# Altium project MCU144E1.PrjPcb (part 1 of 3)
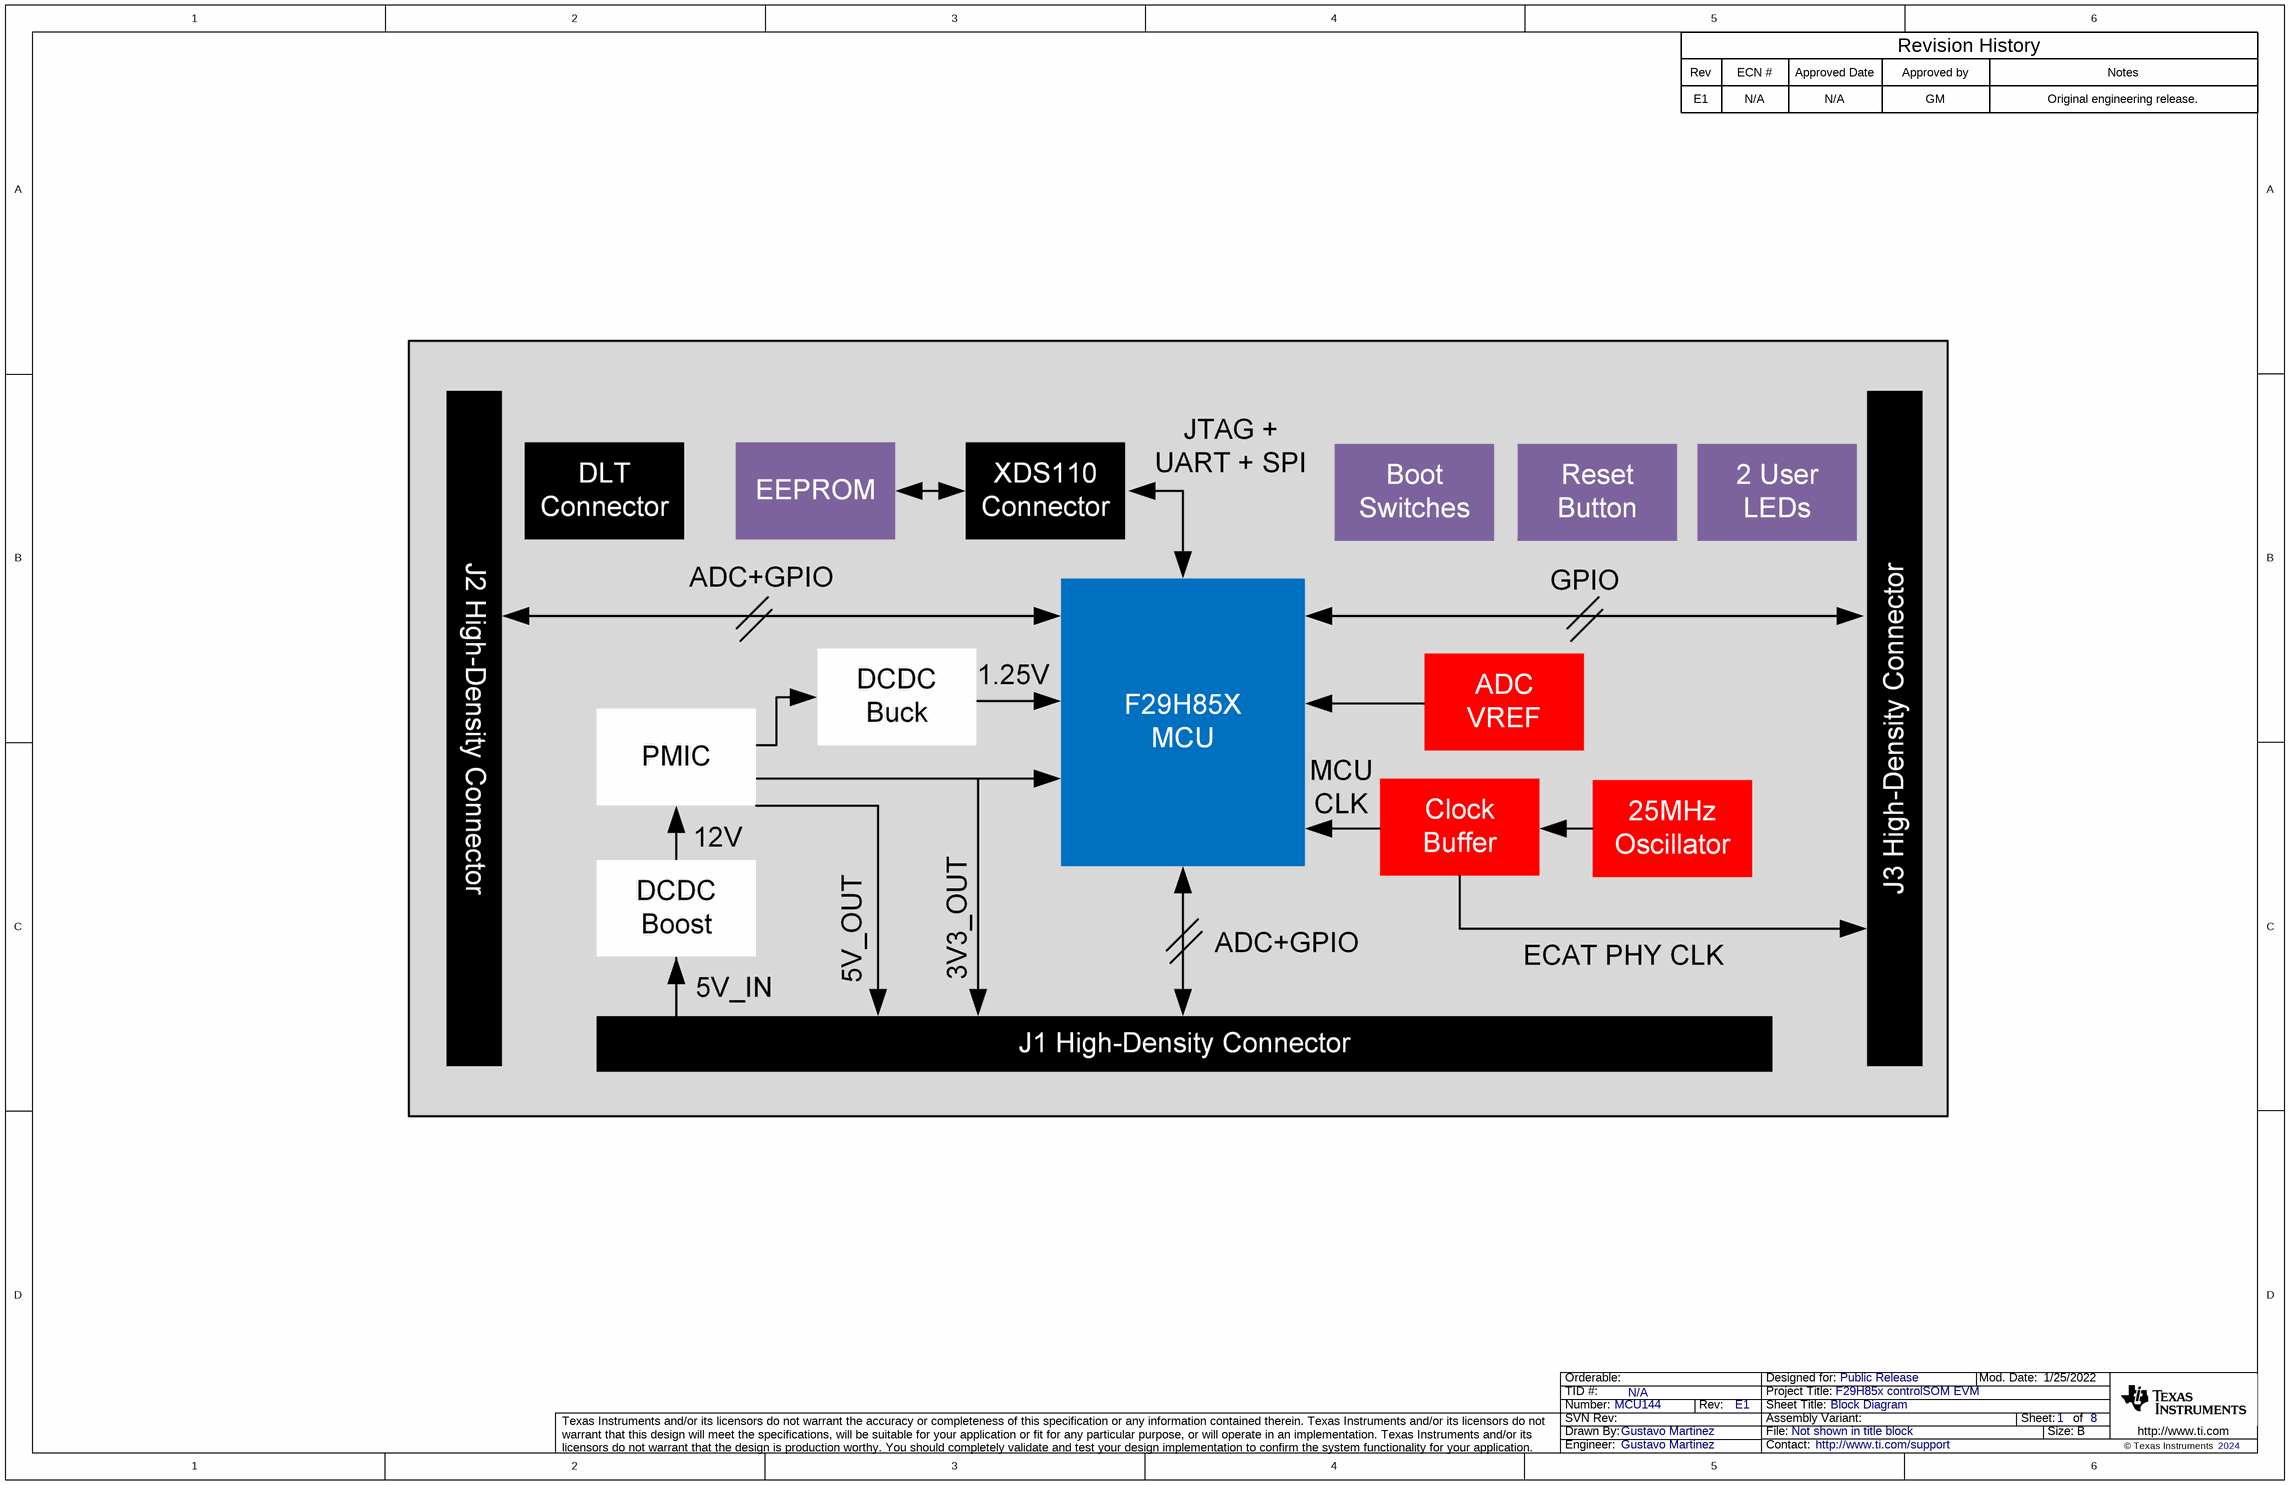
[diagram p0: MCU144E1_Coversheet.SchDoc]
CopyrightYear: 2024; PCB_Layout: Krypton Solutions; PCB_Rev: E1; PRJ_Customer: Public Release; PRJ_Engineer: Gustavo Martinez; PRJ_Number: MCU144; PRJ_Title: F29H85x controlSOM EVM; SCH_Rev: E1; TechSupport: http://www.ti.com/support; TID: N/A
8 sheets, 258 parts. Net scope: global (net labels, ports and power ports of the same name join across sheets).
Board file: MCU144E1.PcbDoc
Sheets:
  MCU144E1_Coversheet.SchDoc
  MCU144E1_GPIO_Power.SchDoc
  MCU144E1_ADC.SchDoc
  MCU144E1_Clock_Reset_Boot.SchDoc
  MCU144E1_SOM_Power.SchDoc
  MCU144E1_Baseboard_Connectors.SchDoc
  MCU144E1_Emulation_Connectors.SchDoc
  MCU144E1_EVM_Hardware.SchDoc

## Sheet MCU144E1_Coversheet.SchDoc: Block Diagram
size 431 x 279 mm; Date: Not shown in title block; ApprovedBy: Not shown in title block; CheckedBy: Not shown in title block; Author: Not shown in title block; CompanyName: Not shown in title block; DrawnBy: Gustavo Martinez; Engineer: Not shown in title block; Organization: Not shown in title block; Address1: Not shown in title block; Address2: Not shown in title block; Address3: Not shown in title block; Address4: Not shown in title block; DocumentNumber: 1; Revision: Use project parameter SCH_Rev; SheetNumber: 1; SheetTotal: 8; PageSetup: Record=PageOptions¦CenterHorizontal=True¦CenterVertical=True¦PrintScale=1.00¦XCorrection=1.00¦YCorrection=1.00¦PrintKind=0¦BorderSize=5000000¦LeftOffset=0¦BottomOffset=0¦Orientation=2¦PaperLength=1000¦PaperWidth=1000¦Scale=100¦PaperSource=15¦PrintQuality=600¦MediaType=1¦DitherType=10¦PaperKind=Letter¦PrintScaleMode=1

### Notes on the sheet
- Rev
- E1
- ECN #
- N/A
- Approved Date
- Approved by
- GM
- Revision History
- Notes
- Original engineering release.

## Sheet MCU144E1_GPIO_Power.SchDoc: GPIO and Power
size 431 x 279 mm; Date: Not shown in title block; ApprovedBy: Not shown in title block; CheckedBy: Not shown in title block; Author: Not shown in title block; CompanyName: Not shown in title block; DrawnBy: Gustavo Martinez; Engineer: Not shown in title block; Organization: Not shown in title block; Address1: Not shown in title block; Address2: Not shown in title block; Address3: Not shown in title block; Address4: Not shown in title block; DocumentNumber: 8; Revision: Use project parameter SCH_Rev; SheetNumber: 2; SheetTotal: 8; PageSetup: Record=PageOptions¦CenterHorizontal=True¦CenterVertical=True¦PrintScale=1.00¦XCorrection=1.00¦YCorrection=1.00¦PrintKind=0¦BorderSize=5000000¦LeftOffset=0¦BottomOffset=0¦Orientation=2¦PaperLength=1000¦PaperWidth=1000¦Scale=100¦PaperSource=15¦PrintQuality=600¦MediaType=1¦DitherType=10¦PaperKind=Letter¦PrintScaleMode=1
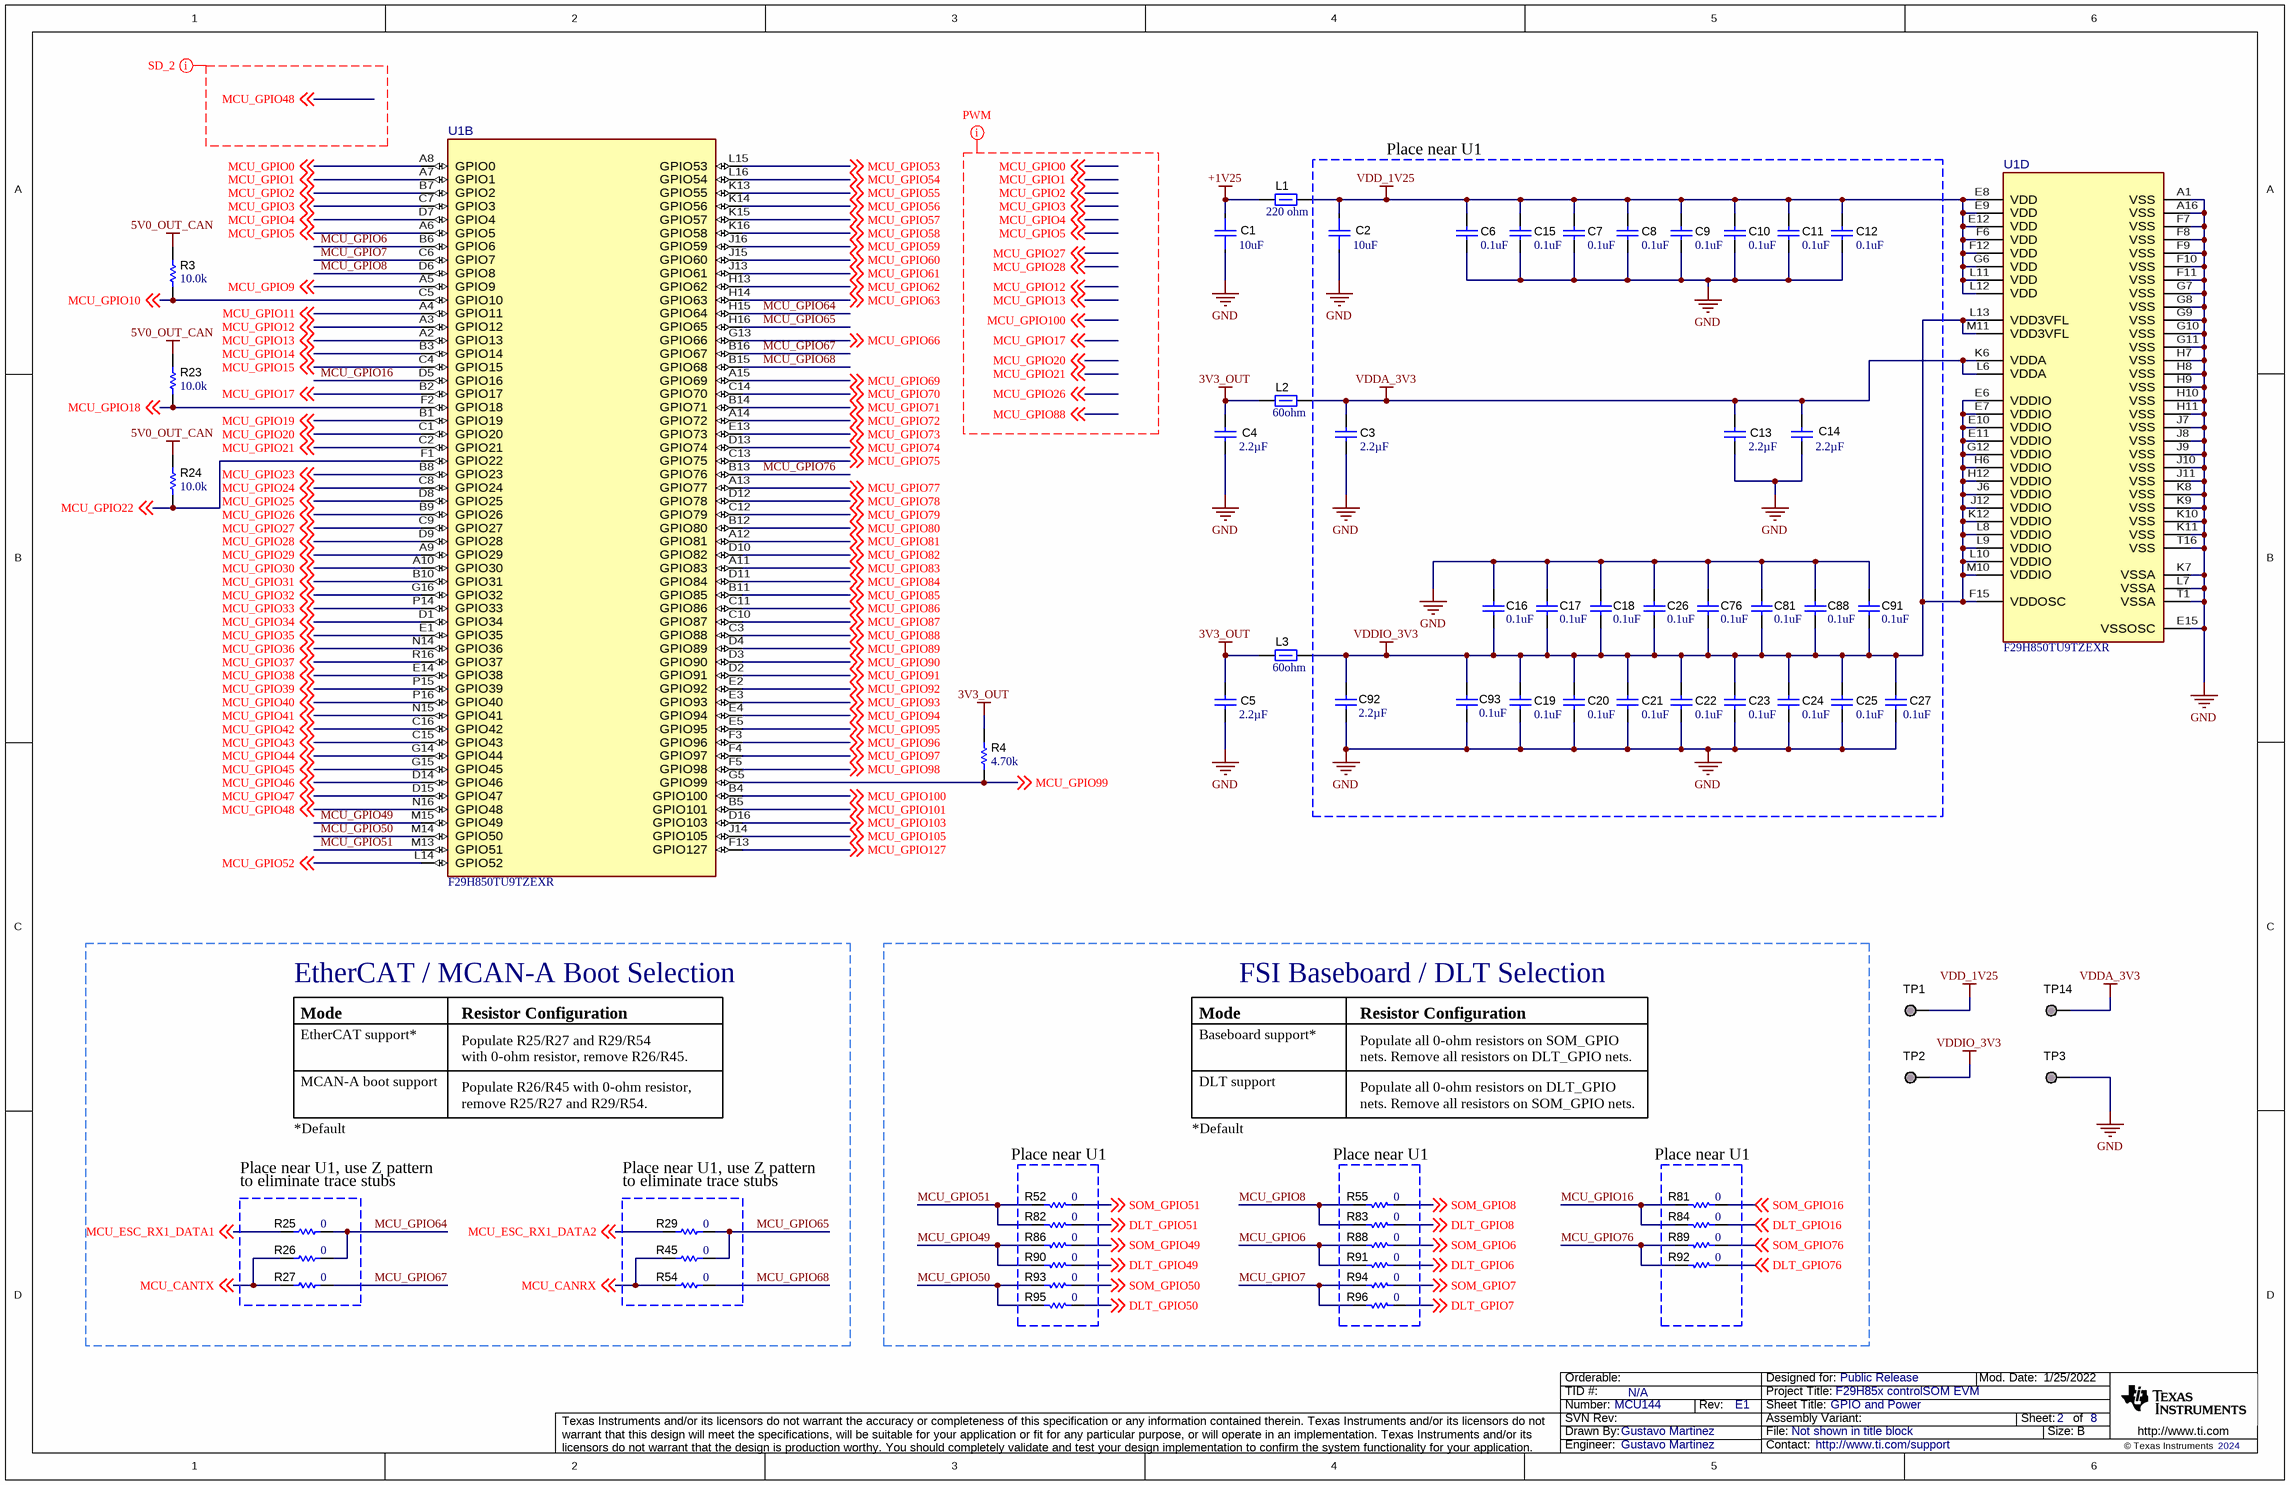
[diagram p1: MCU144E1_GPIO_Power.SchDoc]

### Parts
C1  ValueDisplayed: 10uF  [FP-GRM155R61A106ME18D_0402-MFG]  (hidden comment: GRM155R61A106ME18D)
C2  ValueDisplayed: 10uF  [FP-GRM155R61A106ME18D_0402-MFG]  (hidden comment: GRM155R61A106ME18D)
C3  ValueDisplayed: 2.2µF  [0402]  (hidden comment: GRM155R61E225ME15D)
C4  ValueDisplayed: 2.2µF  [0402]  (hidden comment: GRM155R61E225ME15D)
C5  ValueDisplayed: 2.2µF  [0402]  (hidden comment: GRM155R61E225ME15D)
C6  ValueDisplayed: 0.1uF  [0402]  (hidden comment: GRM155R71E104KE14D)
C7  ValueDisplayed: 0.1uF  [0402]  (hidden comment: GRM155R71E104KE14D)
C8  ValueDisplayed: 0.1uF  [0402]  (hidden comment: GRM155R71E104KE14D)
C9  ValueDisplayed: 0.1uF  [0402]  (hidden comment: GRM155R71E104KE14D)
C10  ValueDisplayed: 0.1uF  [0402]  (hidden comment: GRM155R71E104KE14D)
C11  ValueDisplayed: 0.1uF  [0402]  (hidden comment: GRM155R71E104KE14D)
C12  ValueDisplayed: 0.1uF  [0402]  (hidden comment: GRM155R71E104KE14D)
C13  ValueDisplayed: 2.2µF  [0402]  (hidden comment: GRM155R61E225ME15D)
C14  ValueDisplayed: 2.2µF  [0402]  (hidden comment: GRM155R61E225ME15D)
C15  ValueDisplayed: 0.1uF  [0402]  (hidden comment: GRM155R71E104KE14D)
C16  ValueDisplayed: 0.1uF  [0402]  (hidden comment: GRM155R71E104KE14D)
C17  ValueDisplayed: 0.1uF  [0402]  (hidden comment: GRM155R71E104KE14D)
C18  ValueDisplayed: 0.1uF  [0402]  (hidden comment: GRM155R71E104KE14D)
C19  ValueDisplayed: 0.1uF  [0402]  (hidden comment: GRM155R71E104KE14D)
C20  ValueDisplayed: 0.1uF  [0402]  (hidden comment: GRM155R71E104KE14D)
C21  ValueDisplayed: 0.1uF  [0402]  (hidden comment: GRM155R71E104KE14D)
C22  ValueDisplayed: 0.1uF  [0402]  (hidden comment: GRM155R71E104KE14D)
C23  ValueDisplayed: 0.1uF  [0402]  (hidden comment: GRM155R71E104KE14D)
C24  ValueDisplayed: 0.1uF  [0402]  (hidden comment: GRM155R71E104KE14D)
C25  ValueDisplayed: 0.1uF  [0402]  (hidden comment: GRM155R71E104KE14D)
C26  ValueDisplayed: 0.1uF  [0402]  (hidden comment: GRM155R71E104KE14D)
C27  ValueDisplayed: 0.1uF  [0402]  (hidden comment: GRM155R71E104KE14D)
C76  ValueDisplayed: 0.1uF  [0402]  (hidden comment: GRM155R71E104KE14D)
C81  ValueDisplayed: 0.1uF  [0402]  (hidden comment: GRM155R71E104KE14D)
C88  ValueDisplayed: 0.1uF  [0402]  (hidden comment: GRM155R71E104KE14D)
C91  ValueDisplayed: 0.1uF  [0402]  (hidden comment: GRM155R71E104KE14D)
C92  ValueDisplayed: 2.2µF  [0402]  (hidden comment: GRM155R61E225ME15D)
C93  ValueDisplayed: 0.1uF  [0402]  (hidden comment: GRM155R71E104KE14D)
L1  value 220 ohm  [0805_HV]  (hidden comment: BLM21PG221SN1D)
L2  60ohm  [0603]
L3  60ohm  [0603]
R3  value 10.0k  [0402]  (hidden comment: AC0402FR-0710KL)
R4  ValueDisplayed: 4.70k  [0402]  (hidden comment: CRG0402F4K7)
R23  value 10.0k  [0402]  (hidden comment: AC0402FR-0710KL)
R24  value 10.0k  [0402]  (hidden comment: AC0402FR-0710KL)
R25  ValueDisplayed: 0  [0402]  (hidden comment: CRCW04020000Z0ED)
R26  ValueDisplayed: 0  [0402]  (hidden comment: CRCW04020000Z0ED)
R27  ValueDisplayed: 0  [0402]  (hidden comment: CRCW04020000Z0ED)
R29  ValueDisplayed: 0  [0402]  (hidden comment: CRCW04020000Z0ED)
R45  ValueDisplayed: 0  [0402]  (hidden comment: CRCW04020000Z0ED)
R52  ValueDisplayed: 0  [0402]  (hidden comment: CRCW04020000Z0ED)
R54  ValueDisplayed: 0  [0402]  (hidden comment: CRCW04020000Z0ED)
R55  ValueDisplayed: 0  [0402]  (hidden comment: CRCW04020000Z0ED)
R81  ValueDisplayed: 0  [0402]  (hidden comment: CRCW04020000Z0ED)
R82  ValueDisplayed: 0  [0402]  (hidden comment: CRCW04020000Z0ED)
R83  ValueDisplayed: 0  [0402]  (hidden comment: CRCW04020000Z0ED)
R84  ValueDisplayed: 0  [0402]  (hidden comment: CRCW04020000Z0ED)
R86  ValueDisplayed: 0  [0402]  (hidden comment: CRCW04020000Z0ED)
R88  ValueDisplayed: 0  [0402]  (hidden comment: CRCW04020000Z0ED)
R89  ValueDisplayed: 0  [0402]  (hidden comment: CRCW04020000Z0ED)
R90  ValueDisplayed: 0  [0402]  (hidden comment: CRCW04020000Z0ED)
R91  ValueDisplayed: 0  [0402]  (hidden comment: CRCW04020000Z0ED)
R92  ValueDisplayed: 0  [0402]  (hidden comment: CRCW04020000Z0ED)
R93  ValueDisplayed: 0  [0402]  (hidden comment: CRCW04020000Z0ED)
R94  ValueDisplayed: 0  [0402]  (hidden comment: CRCW04020000Z0ED)
R95  ValueDisplayed: 0  [0402]  (hidden comment: CRCW04020000Z0ED)
R96  ValueDisplayed: 0  [0402]  (hidden comment: CRCW04020000Z0ED)
TP1  CMP-0078143-4  [TESTPOINT]  (value not drawn)  (no BOM)
TP2  CMP-0078143-4  [TESTPOINT]  (value not drawn)  (no BOM)
TP3  CMP-0078143-4  [TESTPOINT]  (value not drawn)  (no BOM)
TP14  CMP-0078143-4  [TESTPOINT]  (value not drawn)  (no BOM)
U1  F29H850TU9TZEXR  [ZEX0256A-MFG]  (parts B,D of 4)

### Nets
3V3_OUT: C4.1 C5.1 L2.1 L3.1 R4.2
5V0_OUT_CAN: R3.2 R23.2 R24.2
+1V25: C1.2 L1.1
GND: C1.1 C2.1 C3.2 C4.2 C5.2 C6.2 C7.2 C8.2 C9.2 C10.2 C11.2 C12.2 C13.2 C14.2 C15.2 C16.2 C17.2 C18.2 C19.2 C20.2 C21.2 C22.2 C23.2 C24.2 C25.2 C26.2 C27.2 C76.2 C81.2 C88.2 C91.2 C92.1 C93.1 TP3.1 U1.A1(VSS) U1.A16(VSS) U1.E15(VSSOSC) U1.F7(VSS) U1.F8(VSS) U1.F9(VSS) U1.F10(VSS) U1.F11(VSS) U1.G7(VSS) U1.G8(VSS) U1.G9(VSS) U1.G10(VSS) U1.G11(VSS) U1.H7(VSS) U1.H8(VSS) U1.H9(VSS) U1.H10(VSS) U1.H11(VSS) U1.J7(VSS) U1.J8(VSS) U1.J9(VSS) U1.J10(VSS) U1.J11(VSS) U1.K7(VSSA) U1.K8(VSS) U1.K9(VSS) U1.K10(VSS) U1.K11(VSS) U1.L7(VSSA) U1.T1(VSSA) U1.T16(VSS)
VDD_1V25: C2.2 C6.1 C7.1 C8.1 C9.1 C10.1 C11.1 C12.1 C15.1 L1.2 TP1.1 U1.E8(VDD) U1.E9(VDD) U1.E12(VDD) U1.F6(VDD) U1.F12(VDD) U1.G6(VDD) U1.L11(VDD) U1.L12(VDD)
VDDA_3V3: C3.1 C13.1 C14.1 L2.2 TP14.1 U1.K6(VDDA) U1.L6(VDDA)
VDDIO_3V3: C16.1 C17.1 C18.1 C19.1 C20.1 C21.1 C22.1 C23.1 C24.1 C25.1 C26.1 C27.1 C76.1 C81.1 C88.1 C91.1 C92.2 C93.2 L3.2 TP2.1 U1.E6(VDDIO) U1.E7(VDDIO) U1.E10(VDDIO) U1.E11(VDDIO) U1.F15(VDDOSC) U1.G12(VDDIO) U1.H6(VDDIO) U1.H12(VDDIO) U1.J6(VDDIO) U1.J12(VDDIO) U1.K12(VDDIO) U1.L8(VDDIO) U1.L9(VDDIO) U1.L10(VDDIO) U1.L13(VDD3VFL) U1.M10(VDDIO) U1.M11(VDD3VFL)
DLT_GPIO6: R91.1 ; off-sheet DLT_GPIO6
DLT_GPIO7: R96.1 ; off-sheet DLT_GPIO7
DLT_GPIO8: R83.1 ; off-sheet DLT_GPIO8
DLT_GPIO16: R84.1 ; off-sheet DLT_GPIO16
DLT_GPIO49: R90.1 ; off-sheet DLT_GPIO49
DLT_GPIO50: R95.1 ; off-sheet DLT_GPIO50
DLT_GPIO51: R82.1 ; off-sheet DLT_GPIO51
DLT_GPIO76: R92.1 ; off-sheet DLT_GPIO76
MCU_CANRX: R45.1 R54.1 ; off-sheet MCU_CANRX
MCU_CANTX: R26.1 R27.1 ; off-sheet MCU_CANTX
MCU_ESC_RX1_DATA1: R25.1 ; off-sheet MCU_ESC_RX1_DATA1
MCU_ESC_RX1_DATA2: R29.1 ; off-sheet MCU_ESC_RX1_DATA2
MCU_GPIO0: U1.A8(GPIO0) ; off-sheet MCU_GPIO0
MCU_GPIO1: U1.A7(GPIO1) ; off-sheet MCU_GPIO1
MCU_GPIO2: U1.B7(GPIO2) ; off-sheet MCU_GPIO2
MCU_GPIO3: U1.C7(GPIO3) ; off-sheet MCU_GPIO3
MCU_GPIO4: U1.D7(GPIO4) ; off-sheet MCU_GPIO4
MCU_GPIO5: U1.A6(GPIO5) ; off-sheet MCU_GPIO5
MCU_GPIO6: R88.2 R91.2 U1.B6(GPIO6)
MCU_GPIO7: R94.2 R96.2 U1.C6(GPIO7)
MCU_GPIO8: R55.2 R83.2 U1.D6(GPIO8)
MCU_GPIO9: U1.A5(GPIO9) ; off-sheet MCU_GPIO9
MCU_GPIO10: R3.1 U1.C5(GPIO10) ; off-sheet MCU_GPIO10
MCU_GPIO11: U1.A4(GPIO11) ; off-sheet MCU_GPIO11
MCU_GPIO12: U1.A3(GPIO12) ; off-sheet MCU_GPIO12
MCU_GPIO13: U1.A2(GPIO13) ; off-sheet MCU_GPIO13
MCU_GPIO14: U1.B3(GPIO14) ; off-sheet MCU_GPIO14
MCU_GPIO15: U1.C4(GPIO15) ; off-sheet MCU_GPIO15
MCU_GPIO16: R81.2 R84.2 U1.D5(GPIO16)
MCU_GPIO17: U1.B2(GPIO17) ; off-sheet MCU_GPIO17
MCU_GPIO18: R23.1 U1.F2(GPIO18) ; off-sheet MCU_GPIO18
MCU_GPIO19: U1.B1(GPIO19) ; off-sheet MCU_GPIO19
MCU_GPIO20: U1.C1(GPIO20) ; off-sheet MCU_GPIO20
MCU_GPIO21: U1.C2(GPIO21) ; off-sheet MCU_GPIO21
MCU_GPIO22: R24.1 U1.F1(GPIO22) ; off-sheet MCU_GPIO22
MCU_GPIO23: U1.B8(GPIO23) ; off-sheet MCU_GPIO23
MCU_GPIO24: U1.C8(GPIO24) ; off-sheet MCU_GPIO24
MCU_GPIO25: U1.D8(GPIO25) ; off-sheet MCU_GPIO25
MCU_GPIO26: U1.B9(GPIO26) ; off-sheet MCU_GPIO26
MCU_GPIO27: U1.C9(GPIO27) ; off-sheet MCU_GPIO27
MCU_GPIO28: U1.D9(GPIO28) ; off-sheet MCU_GPIO28
MCU_GPIO29: U1.A9(GPIO29) ; off-sheet MCU_GPIO29
MCU_GPIO30: U1.A10(GPIO30) ; off-sheet MCU_GPIO30
MCU_GPIO31: U1.B10(GPIO31) ; off-sheet MCU_GPIO31
MCU_GPIO32: U1.G16(GPIO32) ; off-sheet MCU_GPIO32
MCU_GPIO33: U1.P14(GPIO33) ; off-sheet MCU_GPIO33
MCU_GPIO34: U1.D1(GPIO34) ; off-sheet MCU_GPIO34
MCU_GPIO35: U1.E1(GPIO35) ; off-sheet MCU_GPIO35
MCU_GPIO36: U1.N14(GPIO36) ; off-sheet MCU_GPIO36
MCU_GPIO37: U1.R16(GPIO37) ; off-sheet MCU_GPIO37
MCU_GPIO38: U1.E14(GPIO38) ; off-sheet MCU_GPIO38
MCU_GPIO39: U1.P15(GPIO39) ; off-sheet MCU_GPIO39
MCU_GPIO40: U1.P16(GPIO40) ; off-sheet MCU_GPIO40
MCU_GPIO41: U1.N15(GPIO41) ; off-sheet MCU_GPIO41
MCU_GPIO42: U1.C16(GPIO42) ; off-sheet MCU_GPIO42
MCU_GPIO43: U1.C15(GPIO43) ; off-sheet MCU_GPIO43
MCU_GPIO44: U1.G14(GPIO44) ; off-sheet MCU_GPIO44
MCU_GPIO45: U1.G15(GPIO45) ; off-sheet MCU_GPIO45
MCU_GPIO46: U1.D14(GPIO46) ; off-sheet MCU_GPIO46
MCU_GPIO47: U1.D15(GPIO47) ; off-sheet MCU_GPIO47
MCU_GPIO48: U1.N16(GPIO48) ; off-sheet MCU_GPIO48
MCU_GPIO49: R86.2 R90.2 U1.M15(GPIO49)
MCU_GPIO50: R93.2 R95.2 U1.M14(GPIO50)
MCU_GPIO51: R52.2 R82.2 U1.M13(GPIO51)
MCU_GPIO52: U1.L14(GPIO52) ; off-sheet MCU_GPIO52
MCU_GPIO53: U1.L15(GPIO53) ; off-sheet MCU_GPIO53
MCU_GPIO54: U1.L16(GPIO54) ; off-sheet MCU_GPIO54
MCU_GPIO55: U1.K13(GPIO55) ; off-sheet MCU_GPIO55
MCU_GPIO56: U1.K14(GPIO56) ; off-sheet MCU_GPIO56
MCU_GPIO57: U1.K15(GPIO57) ; off-sheet MCU_GPIO57
MCU_GPIO58: U1.K16(GPIO58) ; off-sheet MCU_GPIO58
MCU_GPIO59: U1.J16(GPIO59) ; off-sheet MCU_GPIO59
MCU_GPIO60: U1.J15(GPIO60) ; off-sheet MCU_GPIO60
MCU_GPIO61: U1.J13(GPIO61) ; off-sheet MCU_GPIO61
MCU_GPIO62: U1.H13(GPIO62) ; off-sheet MCU_GPIO62
MCU_GPIO63: U1.H14(GPIO63) ; off-sheet MCU_GPIO63
MCU_GPIO64: R25.2 R26.2 U1.H15(GPIO64)
MCU_GPIO65: R29.2 R45.2 U1.H16(GPIO65)
MCU_GPIO66: U1.G13(GPIO66) ; off-sheet MCU_GPIO66
MCU_GPIO67: R27.2 U1.B16(GPIO67)
MCU_GPIO68: R54.2 U1.B15(GPIO68)
MCU_GPIO69: U1.A15(GPIO69) ; off-sheet MCU_GPIO69
MCU_GPIO70: U1.C14(GPIO70) ; off-sheet MCU_GPIO70
MCU_GPIO71: U1.B14(GPIO71) ; off-sheet MCU_GPIO71
MCU_GPIO72: U1.A14(GPIO72) ; off-sheet MCU_GPIO72
MCU_GPIO73: U1.E13(GPIO73) ; off-sheet MCU_GPIO73
MCU_GPIO74: U1.D13(GPIO74) ; off-sheet MCU_GPIO74
MCU_GPIO75: U1.C13(GPIO75) ; off-sheet MCU_GPIO75
MCU_GPIO76: R89.2 R92.2 U1.B13(GPIO76)
MCU_GPIO77: U1.A13(GPIO77) ; off-sheet MCU_GPIO77
MCU_GPIO78: U1.D12(GPIO78) ; off-sheet MCU_GPIO78
MCU_GPIO79: U1.C12(GPIO79) ; off-sheet MCU_GPIO79
MCU_GPIO80: U1.B12(GPIO80) ; off-sheet MCU_GPIO80
MCU_GPIO81: U1.A12(GPIO81) ; off-sheet MCU_GPIO81
MCU_GPIO82: U1.D10(GPIO82) ; off-sheet MCU_GPIO82
MCU_GPIO83: U1.A11(GPIO83) ; off-sheet MCU_GPIO83
MCU_GPIO84: U1.D11(GPIO84) ; off-sheet MCU_GPIO84
MCU_GPIO85: U1.B11(GPIO85) ; off-sheet MCU_GPIO85
MCU_GPIO86: U1.C11(GPIO86) ; off-sheet MCU_GPIO86
MCU_GPIO87: U1.C10(GPIO87) ; off-sheet MCU_GPIO87
MCU_GPIO88: U1.C3(GPIO88) ; off-sheet MCU_GPIO88
MCU_GPIO89: U1.D4(GPIO89) ; off-sheet MCU_GPIO89
MCU_GPIO90: U1.D3(GPIO90) ; off-sheet MCU_GPIO90
MCU_GPIO91: U1.D2(GPIO91) ; off-sheet MCU_GPIO91
MCU_GPIO92: U1.E2(GPIO92) ; off-sheet MCU_GPIO92
MCU_GPIO93: U1.E3(GPIO93) ; off-sheet MCU_GPIO93
MCU_GPIO94: U1.E4(GPIO94) ; off-sheet MCU_GPIO94
MCU_GPIO95: U1.E5(GPIO95) ; off-sheet MCU_GPIO95
MCU_GPIO96: U1.F3(GPIO96) ; off-sheet MCU_GPIO96
MCU_GPIO97: U1.F4(GPIO97) ; off-sheet MCU_GPIO97
MCU_GPIO98: U1.F5(GPIO98) ; off-sheet MCU_GPIO98
MCU_GPIO99: R4.1 U1.G5(GPIO99) ; off-sheet MCU_GPIO99
MCU_GPIO100: U1.B4(GPIO100) ; off-sheet MCU_GPIO100
MCU_GPIO101: U1.B5(GPIO101) ; off-sheet MCU_GPIO101
MCU_GPIO103: U1.D16(GPIO103) ; off-sheet MCU_GPIO103
MCU_GPIO105: U1.J14(GPIO105) ; off-sheet MCU_GPIO105
MCU_GPIO127: U1.F13(GPIO127) ; off-sheet MCU_GPIO127
SOM_GPIO6: R88.1 ; off-sheet SOM_GPIO6
SOM_GPIO7: R94.1 ; off-sheet SOM_GPIO7
SOM_GPIO8: R55.1 ; off-sheet SOM_GPIO8
SOM_GPIO16: R81.1 ; off-sheet SOM_GPIO16
SOM_GPIO49: R86.1 ; off-sheet SOM_GPIO49
SOM_GPIO50: R93.1 ; off-sheet SOM_GPIO50
SOM_GPIO51: R52.1 ; off-sheet SOM_GPIO51
SOM_GPIO76: R89.1 ; off-sheet SOM_GPIO76

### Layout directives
net class SD_2: MCU_GPIO48
net class PWM: MCU_GPIO0, MCU_GPIO1, MCU_GPIO2, MCU_GPIO3, MCU_GPIO4, MCU_GPIO5, MCU_GPIO12, MCU_GPIO13, MCU_GPIO17, MCU_GPIO20, MCU_GPIO21, MCU_GPIO26, MCU_GPIO27, MCU_GPIO28, MCU_GPIO88, MCU_GPIO100

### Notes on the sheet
- Place near U1
- EtherCAT / MCAN-A Boot Selection
- Mode
- Resistor Configuration
- FSI Baseboard / DLT Selection
- EtherCAT support*
- MCAN-A boot support
- Populate R25/R27 and R29/R54
  with 0-ohm resistor, remove R26/R45.
- Populate R26/R45 with 0-ohm resistor, remove R25/R27 and R29/R54.
- Baseboard support*
- DLT support
- Populate all 0-ohm resistors on SOM_GPIO nets. Remove all resistors on DLT_GPIO nets.
- Populate all 0-ohm resistors on DLT_GPIO nets. Remove all resistors on SOM_GPIO nets.
- *Default
- Place near U1, use Z pattern
- (near R25) to eliminate trace stubs
- (near R29) to eliminate trace stubs

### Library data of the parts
C1 C2 = CMP-0120207-1: 10 µF ±20% 10V Ceramic Capacitor X5R 0402 (1005 Metric); Manufacturer: Murata; Cap_F: 10µF; TempCo: 15%; SizeZ_mm: 0.7mm; Value: 10µF; AEC Qualified: No
C3-C5 C13 C14 C92 = CMP-0081010-1: CAP, CERM, 2.2 µF, 25 V,+/- 20%, X5R, 0402; Manufacturer: MuRata; TaMin_C: -55°C; Polarized: N; SizeAreaWB_mm2: 3; U/M: EA; Value: 2.2uF; TaMax_C: 85°C; SizeZ_mm: 0.6; SizeX_mm: 1; SizeY_mm: 0.5; Value2: 25V; AEC Category: Q200
C6-C12 C15-C27 C76 C81 C88 C91 C93 = CMP-0006659-2: CAP, CERM, 0.1 uF, 25 V, +/- 10%, X7R, 0402; Manufacturer: MuRata; TaMin_C: -55°C; Polarized: N; SizeAreaWB_mm2: 3; Value1: Unknown; U/M: EA; Value: 0.1uF; TaMax_C: 125°C; SizeZ_mm: 0.6; SizeX_mm: 1; SizeY_mm: 0.5; Value2: 25V; Cap_F: 100nF; AEC Category: Q200
L1 = CMP-0003363-1: Ferrite Bead, 220 ohm @ 100 MHz, 2 A, 0805; Manufacturer: MuRata; ZTyp@100MHz_Ohm: 220; SizeAreaWB_mm2: 6.75; DCR_ohm: 0.045; Value1: 0.045 ohm; Imax_A: 2A; SizeZ_mm: 1.45; SizeX_mm: 2; SizeY_mm: 1.25; SizeArea_mm2: 2.5
L2 L3 = CMP-0003173-2: Ferrite Bead, 60 ohm @ 100 MHz, 3 A, 0603; Manufacturer: Wurth Elektronik; PartNumber: 742792602; Ztyp@1GHz_Ohm: 110.436; ZTyp@100MHz_Ohm: 60; SizeAreaWB_mm2: 4.68; DCR_ohm: 0.04; Value1: 0.04 ohm; Imax_A: 3A; SizeZ_mm: 1; SizeX_mm: 1.6; SizeY_mm: 0.8; SizeArea_mm2: 1.28
R3 R23 R24 = CMP-0077731-1: RES, 10.0 k, 1%, 0.063 W, AEC-Q200 Grade 0, 0402; Manufacturer: Yageo America; Power_W: 63mW; TempCo: 100 ppm/C; Value_Code: 10k0; U/M: EA; EIA_Code: E96; Res_ohm: 10k; SizeX_mm: 1.0; SizeY_mm: 0.5; SizeZ_mm: 0.6; Value2: 0.063W; AEC Qualified: Y; VDC_V: 50V; AEC Grade: 0; AEC Category: Q200
R4 = CMP-0026631-1: RES, 4.70 k, 1%, 0.063 W, 0402; Manufacturer: TE Connectivity; Power_W: 63mW; TempCo: 100 ppm/C; Value_Code: 4k70; U/M: EA; Value: 4.70k; Res_ohm: 4.7k; SizeX_mm: 1; SizeY_mm: 0.5; SizeZ_mm: 0.6; Value2: 0.063W; AEC Qualified: N; AEC Category: Q200
R25-R27 R29 R45 R52 R54 R55 R81-R84 R86 R88-R96 = CMP-0026822-3: RES, 0, 5%, 0.063 W, AEC-Q200 Grade 0, 0402; Manufacturer: Vishay-Dale; Power_W: 63mW; TempCo: 200 ppm/C; Value_Code: 0000; Value: 0; EIA_Code: E24; SizeX_mm: 1; SizeY_mm: 0.5; SizeZ_mm: 0.6; Value2: 0.063W; AEC Qualified: Y; AEC Category: Q200; VDC_V: 50V
TP1-TP3 TP14 = CMP-0078143-4: TEST POINT.  No entry in BOM.
U1 = CMP-0121934-2: Real-Time Microcontroller; Manufacturer: Texas Instruments; SizeZ_mm: 1.3mm; AEC Qualified: No; Core Architecture: C29x; Data Bus Width: 64bits; Frequency_Fixed: 200MHz; Interface: I2C,SPI,UART,CAN,LIN,IrDA,Other; Max Supply Voltage: 3.63V; Memory Size: 4MBytes; Memory Type: FLASH; Min Supply Voltage: 1.14V; Number Of A/D Converters: 5; Number Of Cores: 3; Number Of Ethernet Channels: 1; Number Of I2C Channels: 2; Number Of Pwm Channels: 36; Number Of Timers/Counters: 12; Number Of Uart Channels: 6; Ram Size: 452KBytes; Standoff Height: 0.25mm; TaMax_C: +105°C; TaMin_C: -40°C; TJmax_C: +125°C; AEC Category: Q200; CompType: IC

## Sheet MCU144E1_ADC.SchDoc: ADC
size 431 x 279 mm; DrawnBy: Gustavo Martinez; DocumentNumber: 9; SheetNumber: 3; SheetTotal: 8; PageSetup: Record=PageOptions¦CenterHorizontal=True¦CenterVertical=True¦PrintScale=1.00¦XCorrection=1.00¦YCorrection=1.00¦PrintKind=0¦BorderSize=5000000¦LeftOffset=0¦BottomOffset=0¦Orientation=2¦PaperLength=1000¦PaperWidth=1000¦Scale=100¦PaperSource=15¦PrintQuality=600¦MediaType=1¦DitherType=10¦PaperKind=Letter¦PrintScaleMode=1
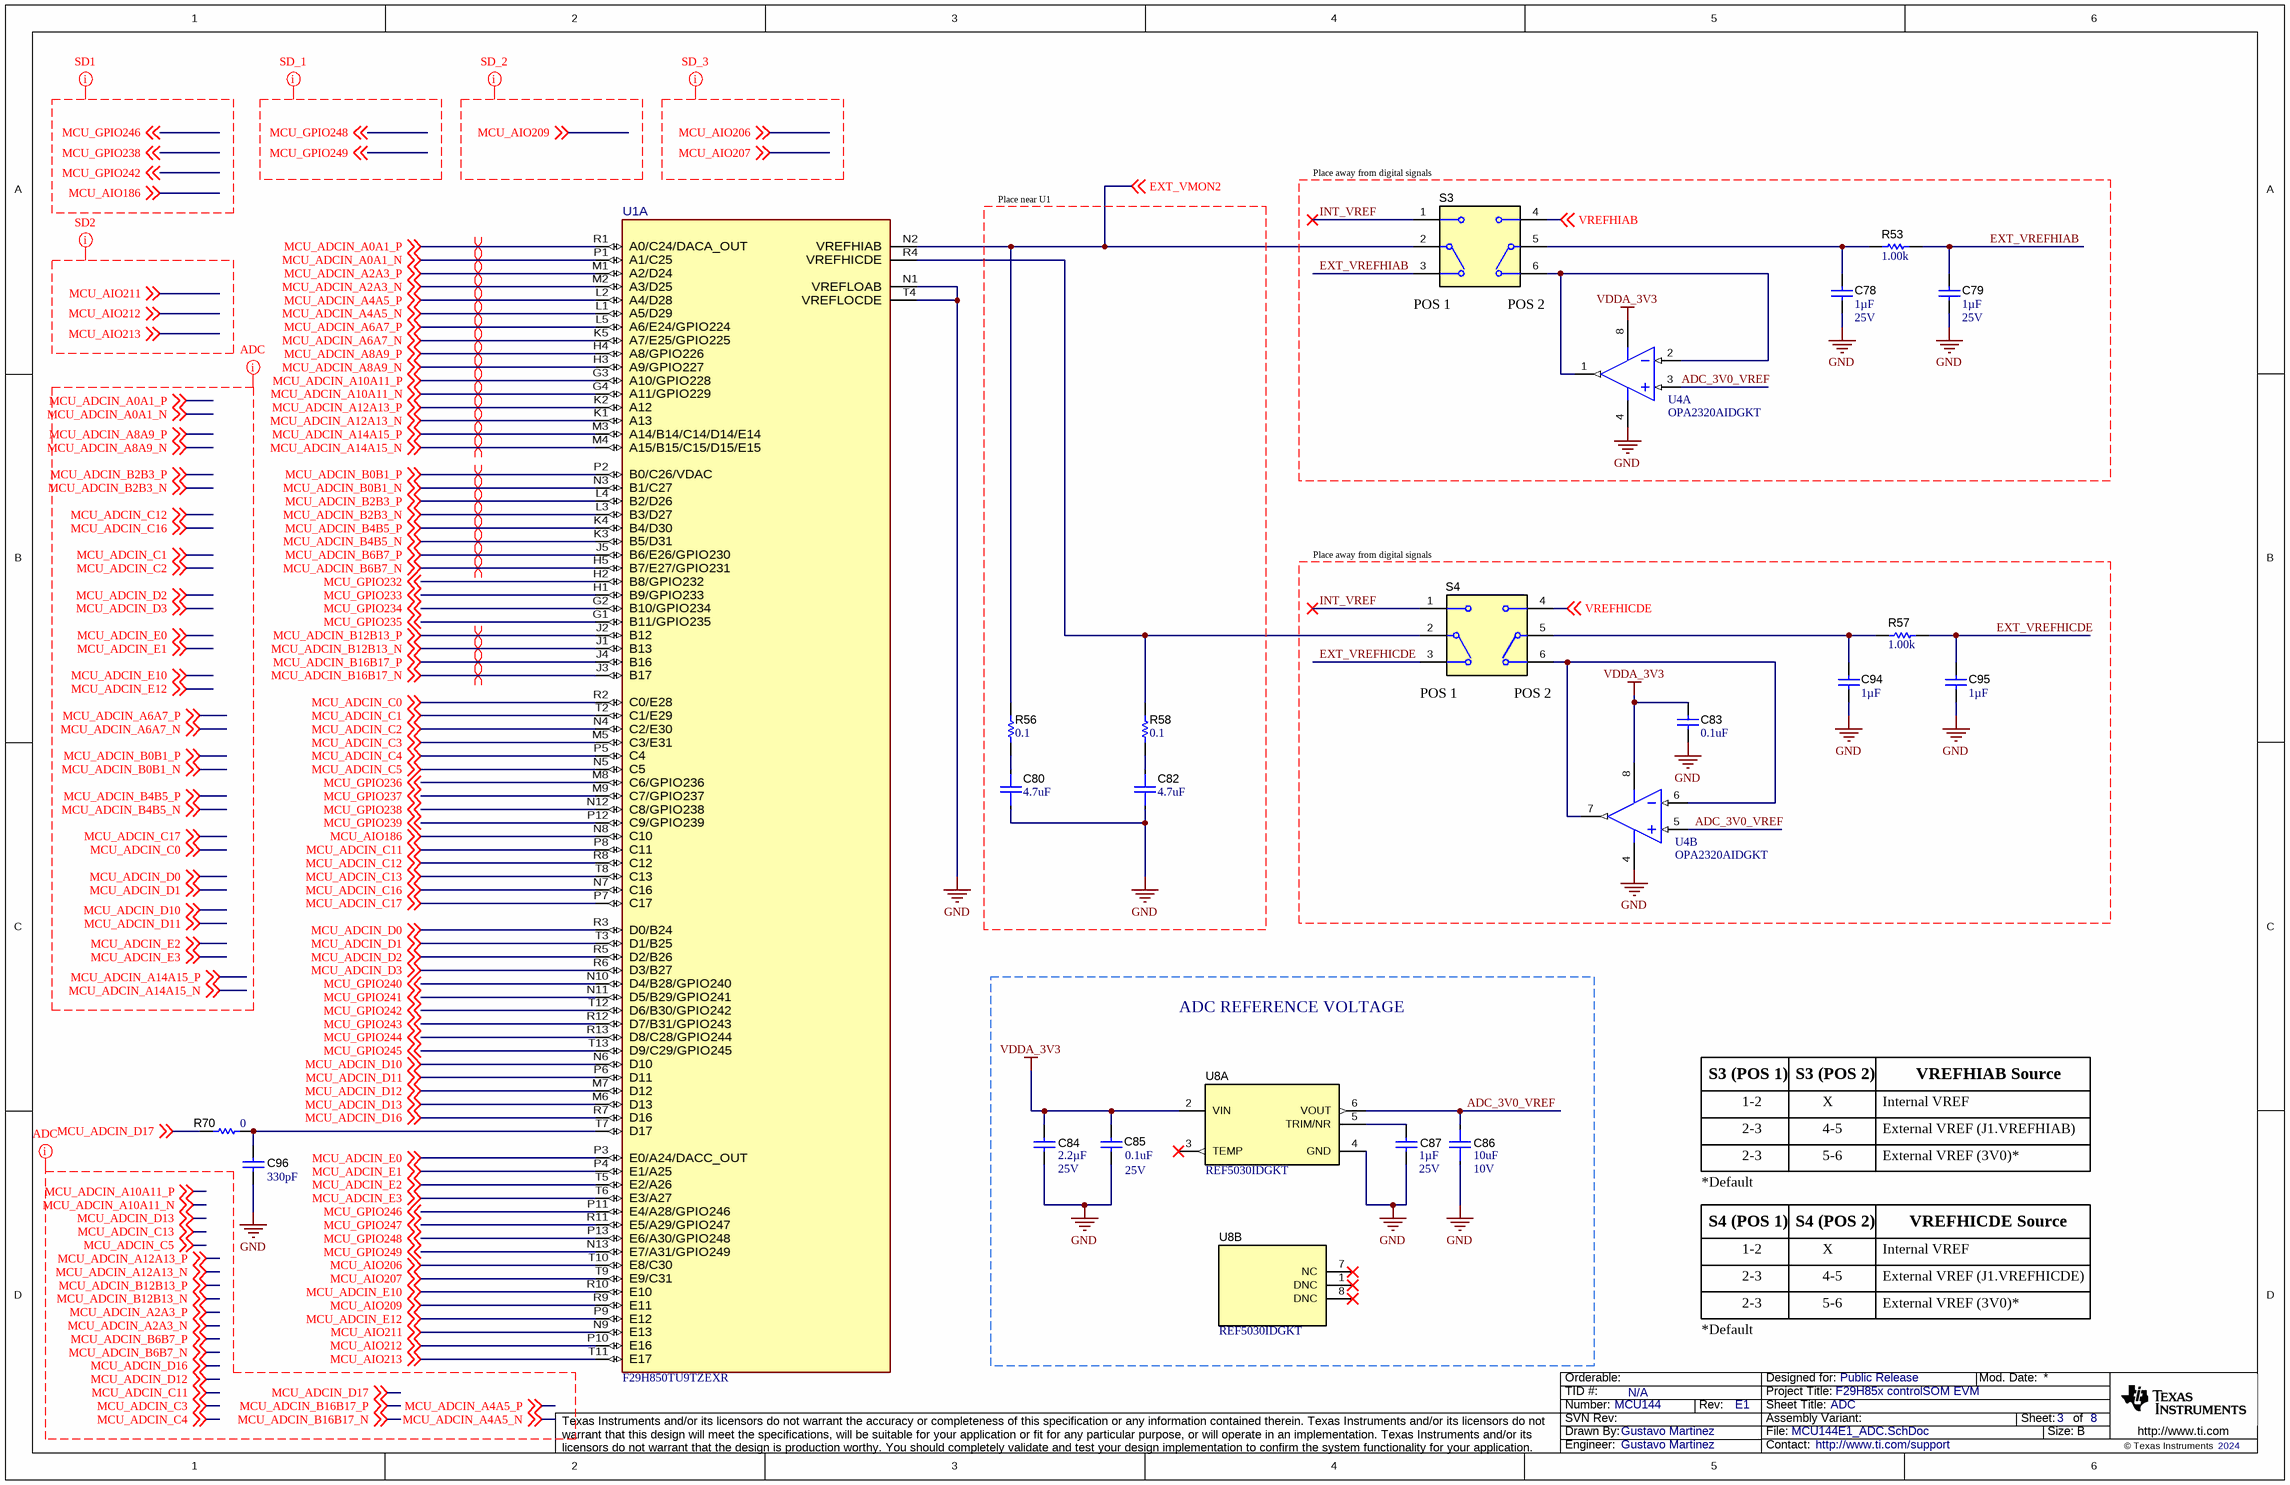
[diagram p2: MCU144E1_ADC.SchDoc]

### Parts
C78  ValueDisplayed: 1µF  VDC_V: 25V  [0402]  (hidden comment: GRM155R61E105KE11D)
C79  ValueDisplayed: 1µF  VDC_V: 25V  [0402]  (hidden comment: GRM155R61E105KE11D)
C80  ValueDisplayed: 4.7uF  [FP-GRM155C61E475ME15D_0402-MFG]  (hidden comment: GRM155C61E475ME15D)
C82  ValueDisplayed: 4.7uF  [FP-GRM155C61E475ME15D_0402-MFG]  (hidden comment: GRM155C61E475ME15D)
C83  ValueDisplayed: 0.1uF  [0402]  (hidden comment: GRM155R71E104KE14D)
C84  Value2: 25V  ValueDisplayed: 2.2µF  [0402]  (hidden comment: GRM155R61E225ME15D)
C85  VDC_V: 25V  ValueDisplayed: 0.1uF  [0402]  (hidden comment: GRM155R71E104KE14D)
C86  VDC_V: 10V  ValueDisplayed: 10uF  [FP-GRM155R61A106ME18D_0402-MFG]  (hidden comment: GRM155R61A106ME18D)
C87  ValueDisplayed: 1µF  VDC_V: 25V  [0402]  (hidden comment: GRM155R61E105KE11D)
C94  ValueDisplayed: 1µF  [0402]  (hidden comment: GRM155R61E105KE11D)
C95  ValueDisplayed: 1µF  [0402]  (hidden comment: GRM155R61E105KE11D)
C96  value 330pF  [0603]  (hidden comment: 885012006060)
R53  ValueDisplayed: 1.00k  [0402]  (hidden comment: ERJ-2RKF1001X)
R56  ValueDisplayed: 0.1  [0402]  (hidden comment: ERJ2BWFR100X)
R57  ValueDisplayed: 1.00k  [0402]  (hidden comment: ERJ-2RKF1001X)
R58  ValueDisplayed: 0.1  [0402]  (hidden comment: ERJ2BWFR100X)
R70  ValueDisplayed: 0  [0603]  (hidden comment: ERJ-3GEY0R00V)
S3  CAS-D20TA  [SW_CAS-D20TA]  (value not drawn)
S4  CAS-D20TA  [SW_CAS-D20TA]  (value not drawn)
U1  F29H850TU9TZEXR  [ZEX0256A-MFG]  (part A of 4)
U4  OPA2320AIDGKT  [DGK0008A_N]  (parts A,B of 2)
U8  REF5030IDGKT  [DGK0008A_N]  (parts A,B of 2)

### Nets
GND: C78.2 C79.2 C80.1 C82.1 C83.2 C84.2 C85.2 C86.1 C87.2 C94.2 C95.2 C96.2 U1.N1(VREFLOAB) U1.T4(VREFLOCDE) U4.4(V-) U8.4(GND)
VDDA_3V3: C83.1 C84.1 C85.1 U4.8(V+) U8.2(VIN)
ADC_3V0_VREF: C86.2 U4.3(IN_A+) U4.5(IN_B+) U8.6(VOUT)
EXT_VMON2: R56.2 S3.2(C) U1.N2(VREFHIAB) ; off-sheet EXT_VMON2
EXT_VREFHIAB: C79.1 R53.2 S3.3
EXT_VREFHICDE: C95.1 R57.2 S4.3
INT_VREF: S3.1 S4.1
MCU_ADCIN_A0A1_N: U1.P1(A1/C25) ; off-sheet MCU_ADCIN_A0A1_N
MCU_ADCIN_A0A1_P: U1.R1(A0/C24/DACA_OUT) ; off-sheet MCU_ADCIN_A0A1_P
MCU_ADCIN_A2A3_N: U1.M2(A3/D25) ; off-sheet MCU_ADCIN_A2A3_N
MCU_ADCIN_A2A3_P: U1.M1(A2/D24) ; off-sheet MCU_ADCIN_A2A3_P
MCU_ADCIN_A4A5_N: U1.L1(A5/D29) ; off-sheet MCU_ADCIN_A4A5_N
MCU_ADCIN_A4A5_P: U1.L2(A4/D28) ; off-sheet MCU_ADCIN_A4A5_P
MCU_ADCIN_A6A7_N: U1.K5(A7/E25/GPIO225) ; off-sheet MCU_ADCIN_A6A7_N
MCU_ADCIN_A6A7_P: U1.L5(A6/E24/GPIO224) ; off-sheet MCU_ADCIN_A6A7_P
MCU_ADCIN_A8A9_N: U1.H3(A9/GPIO227) ; off-sheet MCU_ADCIN_A8A9_N
MCU_ADCIN_A8A9_P: U1.H4(A8/GPIO226) ; off-sheet MCU_ADCIN_A8A9_P
MCU_ADCIN_A10A11_N: U1.G4(A11/GPIO229) ; off-sheet MCU_ADCIN_A10A11_N
MCU_ADCIN_A10A11_P: U1.G3(A10/GPIO228) ; off-sheet MCU_ADCIN_A10A11_P
MCU_ADCIN_A12A13_N: U1.K1(A13) ; off-sheet MCU_ADCIN_A12A13_N
MCU_ADCIN_A12A13_P: U1.K2(A12) ; off-sheet MCU_ADCIN_A12A13_P
MCU_ADCIN_A14A15_N: U1.M4(A15/B15/C15/D15/E15) ; off-sheet MCU_ADCIN_A14A15_N
MCU_ADCIN_A14A15_P: U1.M3(A14/B14/C14/D14/E14) ; off-sheet MCU_ADCIN_A14A15_P
MCU_ADCIN_B0B1_N: U1.N3(B1/C27) ; off-sheet MCU_ADCIN_B0B1_N
MCU_ADCIN_B0B1_P: U1.P2(B0/C26/VDAC) ; off-sheet MCU_ADCIN_B0B1_P
MCU_ADCIN_B2B3_N: U1.L3(B3/D27) ; off-sheet MCU_ADCIN_B2B3_N
MCU_ADCIN_B2B3_P: U1.L4(B2/D26) ; off-sheet MCU_ADCIN_B2B3_P
MCU_ADCIN_B4B5_N: U1.K3(B5/D31) ; off-sheet MCU_ADCIN_B4B5_N
MCU_ADCIN_B4B5_P: U1.K4(B4/D30) ; off-sheet MCU_ADCIN_B4B5_P
MCU_ADCIN_B6B7_N: U1.H5(B7/E27/GPIO231) ; off-sheet MCU_ADCIN_B6B7_N
MCU_ADCIN_B6B7_P: U1.J5(B6/E26/GPIO230) ; off-sheet MCU_ADCIN_B6B7_P
MCU_ADCIN_B12B13_N: U1.J1(B13) ; off-sheet MCU_ADCIN_B12B13_N
MCU_ADCIN_B12B13_P: U1.J2(B12) ; off-sheet MCU_ADCIN_B12B13_P
MCU_ADCIN_B16B17_N: U1.J3(B17) ; off-sheet MCU_ADCIN_B16B17_N
MCU_ADCIN_B16B17_P: U1.J4(B16) ; off-sheet MCU_ADCIN_B16B17_P
MCU_ADCIN_C0: U1.R2(C0/E28) ; off-sheet MCU_ADCIN_C0
MCU_ADCIN_C1: U1.T2(C1/E29) ; off-sheet MCU_ADCIN_C1
MCU_ADCIN_C2: U1.N4(C2/E30) ; off-sheet MCU_ADCIN_C2
MCU_ADCIN_C3: U1.M5(C3/E31) ; off-sheet MCU_ADCIN_C3
MCU_ADCIN_C4: U1.P5(C4) ; off-sheet MCU_ADCIN_C4
MCU_ADCIN_C5: U1.N5(C5) ; off-sheet MCU_ADCIN_C5
MCU_ADCIN_C11: U1.P8(C11) ; off-sheet MCU_ADCIN_C11
MCU_ADCIN_C12: U1.R8(C12) ; off-sheet MCU_ADCIN_C12
MCU_ADCIN_C13: U1.T8(C13) ; off-sheet MCU_ADCIN_C13
MCU_ADCIN_C16: U1.N7(C16) ; off-sheet MCU_ADCIN_C16
MCU_ADCIN_C17: U1.P7(C17) ; off-sheet MCU_ADCIN_C17
MCU_ADCIN_D0: U1.R3(D0/B24) ; off-sheet MCU_ADCIN_D0
MCU_ADCIN_D1: U1.T3(D1/B25) ; off-sheet MCU_ADCIN_D1
MCU_ADCIN_D2: U1.R5(D2/B26) ; off-sheet MCU_ADCIN_D2
MCU_ADCIN_D3: U1.R6(D3/B27) ; off-sheet MCU_ADCIN_D3
MCU_ADCIN_D10: U1.N6(D10) ; off-sheet MCU_ADCIN_D10
MCU_ADCIN_D11: U1.P6(D11) ; off-sheet MCU_ADCIN_D11
MCU_ADCIN_D12: U1.M7(D12) ; off-sheet MCU_ADCIN_D12
MCU_ADCIN_D13: U1.M6(D13) ; off-sheet MCU_ADCIN_D13
MCU_ADCIN_D16: U1.R7(D16) ; off-sheet MCU_ADCIN_D16
MCU_ADCIN_D17: R70.1 ; off-sheet MCU_ADCIN_D17
MCU_ADCIN_E0: U1.P3(E0/A24/DACC_OUT) ; off-sheet MCU_ADCIN_E0
MCU_ADCIN_E1: U1.P4(E1/A25) ; off-sheet MCU_ADCIN_E1
MCU_ADCIN_E2: U1.T5(E2/A26) ; off-sheet MCU_ADCIN_E2
MCU_ADCIN_E3: U1.T6(E3/A27) ; off-sheet MCU_ADCIN_E3
MCU_ADCIN_E10: U1.R10(E10) ; off-sheet MCU_ADCIN_E10
MCU_ADCIN_E12: U1.P9(E12) ; off-sheet MCU_ADCIN_E12
MCU_AIO186: U1.N8(C10) ; off-sheet MCU_AIO186
MCU_AIO206: U1.T10(E8/C30) ; off-sheet MCU_AIO206
MCU_AIO207: U1.T9(E9/C31) ; off-sheet MCU_AIO207
MCU_AIO209: U1.R9(E11) ; off-sheet MCU_AIO209
MCU_AIO211: U1.N9(E13) ; off-sheet MCU_AIO211
MCU_AIO212: U1.P10(E16) ; off-sheet MCU_AIO212
MCU_AIO213: U1.T11(E17) ; off-sheet MCU_AIO213
MCU_GPIO232: U1.H2(B8/GPIO232) ; off-sheet MCU_GPIO232
MCU_GPIO233: U1.H1(B9/GPIO233) ; off-sheet MCU_GPIO233
MCU_GPIO234: U1.G2(B10/GPIO234) ; off-sheet MCU_GPIO234
MCU_GPIO235: U1.G1(B11/GPIO235) ; off-sheet MCU_GPIO235
MCU_GPIO236: U1.M8(C6/GPIO236) ; off-sheet MCU_GPIO236
MCU_GPIO237: U1.M9(C7/GPIO237) ; off-sheet MCU_GPIO237
MCU_GPIO238: U1.N12(C8/GPIO238) ; off-sheet MCU_GPIO238
MCU_GPIO239: U1.P12(C9/GPIO239) ; off-sheet MCU_GPIO239
MCU_GPIO240: U1.N10(D4/B28/GPIO240) ; off-sheet MCU_GPIO240
MCU_GPIO241: U1.N11(D5/B29/GPIO241) ; off-sheet MCU_GPIO241
MCU_GPIO242: U1.T12(D6/B30/GPIO242) ; off-sheet MCU_GPIO242
MCU_GPIO243: U1.R12(D7/B31/GPIO243) ; off-sheet MCU_GPIO243
MCU_GPIO244: U1.R13(D8/C28/GPIO244) ; off-sheet MCU_GPIO244
MCU_GPIO245: U1.T13(D9/C29/GPIO245) ; off-sheet MCU_GPIO245
MCU_GPIO246: U1.P11(E4/A28/GPIO246) ; off-sheet MCU_GPIO246
MCU_GPIO247: U1.R11(E5/A29/GPIO247) ; off-sheet MCU_GPIO247
MCU_GPIO248: U1.P13(E6/A30/GPIO248) ; off-sheet MCU_GPIO248
MCU_GPIO249: U1.N13(E7/A31/GPIO249) ; off-sheet MCU_GPIO249
VREFHIAB: S3.4 ; off-sheet VREFHIAB
VREFHICDE: S4.4 ; off-sheet VREFHICDE
NetC78_1: C78.1 R53.1 S3.5(C)
NetC80_2: C80.2 R56.1
NetC82_2: C82.2 R58.1
NetC87_1: C87.1 U8.5(TRIM/NR)
NetC94_1: C94.1 R57.1 S4.5(C)
NetC96_1: C96.1 R70.2 U1.T7(D17)
NetR58_2: R58.2 S4.2(C) U1.R4(VREFHICDE)
NetS3_6: S3.6 U4.1(OUT_A) U4.2(IN_A-)
NetS4_6: S4.6 U4.6(IN_B-) U4.7(OUT_B)

Not connected (* = marked no-connect by the designer): U8 1(DNC)* 3(TEMP)* 7(NC)* 8(DNC)*

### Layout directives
differential pair; differential pair class 100OHM; differential pair class 100OHM: MCU_ADCIN_A0A1_P
differential pair; differential pair class 100OHM: MCU_ADCIN_A0A1_N, MCU_ADCIN_A2A3_N, MCU_ADCIN_A2A3_P, MCU_ADCIN_A4A5_N, MCU_ADCIN_A4A5_P, MCU_ADCIN_A6A7_N, MCU_ADCIN_A6A7_P, MCU_ADCIN_A8A9_N, MCU_ADCIN_A8A9_P, MCU_ADCIN_A10A11_N, MCU_ADCIN_A10A11_P, MCU_ADCIN_A12A13_N, MCU_ADCIN_A12A13_P, MCU_ADCIN_A14A15_N, MCU_ADCIN_A14A15_P, MCU_ADCIN_B0B1_N, MCU_ADCIN_B0B1_P, MCU_ADCIN_B2B3_N, MCU_ADCIN_B2B3_P, MCU_ADCIN_B4B5_N, MCU_ADCIN_B4B5_P, MCU_ADCIN_B6B7_N, MCU_ADCIN_B6B7_P, MCU_ADCIN_B12B13_N, MCU_ADCIN_B12B13_P, MCU_ADCIN_B16B17_N, MCU_ADCIN_B16B17_P
net class SD1: MCU_AIO186, MCU_GPIO238, MCU_GPIO242, MCU_GPIO246
net class SD2: MCU_AIO211, MCU_AIO212, MCU_AIO213
net class SD_1: MCU_GPIO248, MCU_GPIO249
net class SD_2: MCU_AIO209
net class SD_3: MCU_AIO206, MCU_AIO207
net class ADC: GND, MCU_ADCIN_A0A1_N, MCU_ADCIN_A0A1_P, MCU_ADCIN_A2A3_N, MCU_ADCIN_A2A3_P, MCU_ADCIN_A4A5_N, MCU_ADCIN_A4A5_P, MCU_ADCIN_A6A7_N, MCU_ADCIN_A6A7_P, MCU_ADCIN_A8A9_N, MCU_ADCIN_A8A9_P, MCU_ADCIN_A10A11_N, MCU_ADCIN_A10A11_P, MCU_ADCIN_A12A13_N, MCU_ADCIN_A12A13_P, MCU_ADCIN_A14A15_N, MCU_ADCIN_A14A15_P, MCU_ADCIN_B0B1_N, MCU_ADCIN_B0B1_P, MCU_ADCIN_B2B3_N, MCU_ADCIN_B2B3_P, MCU_ADCIN_B4B5_N, MCU_ADCIN_B4B5_P, MCU_ADCIN_B6B7_N, MCU_ADCIN_B6B7_P, MCU_ADCIN_B12B13_N, MCU_ADCIN_B12B13_P, MCU_ADCIN_B16B17_N, MCU_ADCIN_B16B17_P, MCU_ADCIN_C0, MCU_ADCIN_C1, MCU_ADCIN_C2, MCU_ADCIN_C3, MCU_ADCIN_C4, MCU_ADCIN_C5, MCU_ADCIN_C11, MCU_ADCIN_C12, MCU_ADCIN_C13, MCU_ADCIN_C16, MCU_ADCIN_C17, MCU_ADCIN_D0, MCU_ADCIN_D1, MCU_ADCIN_D2, MCU_ADCIN_D3, MCU_ADCIN_D10, MCU_ADCIN_D11, MCU_ADCIN_D12, MCU_ADCIN_D13, MCU_ADCIN_D16, MCU_ADCIN_D17, MCU_ADCIN_E0, MCU_ADCIN_E1, MCU_ADCIN_E2, MCU_ADCIN_E3, MCU_ADCIN_E10, MCU_ADCIN_E12, MCU_AIO206, MCU_AIO207, MCU_AIO209, MCU_AIO211, MCU_AIO212, MCU_AIO213, MCU_GPIO246, MCU_GPIO247, MCU_GPIO248, MCU_GPIO249

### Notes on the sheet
- Place near U1
- (near S3) Place away from digital signals
- (near S3) POS 1
- (near S3) POS 2
- (near S4) Place away from digital signals
- (near S4) POS 1
- (near S4) POS 2
- ADC REFERENCE VOLTAGE
- S3 (POS 1)
- 1-2
- S3 (POS 2)
- X
- Internal VREF
- VREFHIAB Source
- 2-3
- 4-5
- 5-6
- External VREF (3V0)*
- External VREF (J1.VREFHIAB)
- *Default
- S4 (POS 1)
- S4 (POS 2)
- VREFHICDE Source
- External VREF (J1.VREFHICDE)

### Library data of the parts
C78 C79 C87 = CMP-0086061-1: CAP, CERM, 1 µF, 25 V,+/- 10%, X5R, 0402; Manufacturer: MuRata; SizeX_mm: 1; AEC Category: Q200; SizeAreaWB_mm2: 3; U/M: EA; TaMin_C: -55°C; AEC Qualified: N; SizeZ_mm: 0.6; TaMax_C: 85°C; SizeArea_mm2: 0.5; Value: 1uF
C80 C82 = CMP-0120206-1: 4.7 µF ±20% 25V Ceramic Capacitor X5S 0402 (1005 Metric); Manufacturer: Murata; AEC Qualified: No; Cap_F: 4.7µF; SizeZ_mm: 0.7mm; TempCo: 22%; Value: 4.7µF
C83 = CMP-0006659-2: as C6 on sheet MCU144E1_GPIO_Power
C84 = CMP-0081010-1: CAP, CERM, 2.2 µF, 25 V,+/- 20%, X5R, 0402; Manufacturer: MuRata; TaMin_C: -55°C; Polarized: N; SizeAreaWB_mm2: 3; U/M: EA; Value: 2.2uF; TaMax_C: 85°C; SizeZ_mm: 0.6; SizeX_mm: 1; SizeY_mm: 0.5; AEC Category: Q200
C85 = CMP-0006659-2: CAP, CERM, 0.1 uF, 25 V, +/- 10%, X7R, 0402; Manufacturer: MuRata; TaMin_C: -55°C; Polarized: N; SizeAreaWB_mm2: 3; Value1: Unknown; U/M: EA; Value: 0.1uF; TaMax_C: 125°C; SizeZ_mm: 0.6; SizeX_mm: 1; SizeY_mm: 0.5; Cap_F: 100nF; AEC Category: Q200
C86 = CMP-0120207-1: 10 µF ±20% 10V Ceramic Capacitor X5R 0402 (1005 Metric); Manufacturer: Murata; TempCo: 15%; Value: 10µF; SizeZ_mm: 0.7mm; AEC Qualified: No
C94 C95 = CMP-0086061-1: CAP, CERM, 1 µF, 25 V,+/- 10%, X5R, 0402; Manufacturer: MuRata; SizeX_mm: 1; AEC Category: Q200; SizeAreaWB_mm2: 3; U/M: EA; Value2: 25V; TaMin_C: -55°C; AEC Qualified: N; SizeZ_mm: 0.6; TaMax_C: 85°C; SizeArea_mm2: 0.5; Value: 1uF
C96 = CMP-0006823-4: CAP, CERM, 330 pF, 50 V, +/- 5%, C0G/NP0, 0603; Manufacturer: Wurth Elektronik; TaMin_C: -55°C; Polarized: N; SizeAreaWB_mm2: 4.68; Value1: Unknown; U/M: EA; TaMax_C: 125°C; SizeZ_mm: 1; SizeX_mm: 1.6; SizeY_mm: 0.8; Value2: 50V; SizeArea_mm2: 1.28; AEC Category: Q200
R53 R57 = CMP-0026657-1: RES, 1.00 k, 1%, 0.1 W, 0402; Manufacturer: Panasonic; Power_W: 100mW; TempCo: 100 ppm/C; Value_Code: 1k00; U/M: EA; Value: 1.00k; EIA_Code: E96; Res_ohm: 1k; SizeX_mm: 1; SizeY_mm: 0.5; SizeZ_mm: 0.6; Value2: 0.1W; VDC_V: 50V; AEC Category: Q200
R56 R58 = CMP-0078660-1: RES, 0.1, 1%, 0.25 W, 0402; Manufacturer: Panasonic; Power_W: 250mW; TempCo: 300 ppm/C; Value_Code: R100; Value: 0.1; EIA_Code: E96; Res_ohm: 1d; SizeX_mm: 1; SizeY_mm: 0.5; SizeZ_mm: 0.6; Value2: 0.25W; AEC Qualified: N; AEC Category: Q200
R70 = CMP-0025874-4: RES, 0, 5%, 0.1 W, AEC-Q200 Grade 0, 0603; Manufacturer: Panasonic; Power_W: 100mW; TempCo: 600 ppm/C; Value_Code: 0000; Value: 0; EIA_Code: E24; SizeX_mm: 1.6; SizeY_mm: 0.8; SizeZ_mm: 1; Value2: 0.1W; SizeArea_mm2: 1.28; AEC Qualified: Y; VDC_V: 50V; AEC Category: Q200; SizeAreaWB_mm2: 4.68
S3 S4 = CMP-0002233-1: Switch, Dual SPDT,  2 Pos, 0.1A, 6VDC, SMD; Manufacturer: Copal Electronics; CurrentRating_mA: 100A; SwitchFunction: On-On; VDC_V: 6V; PositionCount: 2
U1 = CMP-0121934-2: as U1 on sheet MCU144E1_GPIO_Power
U4 = CMP-0040680-2: Precision, Zero-Crossover, 20MHz, 0.9pA Ib, RRIO, CMOS Operational Amplifier, DGK0008A (VSSOP-8); Manufacturer: Texas Instruments; Vio (25C)(Max)(mV): 0.15; Sub Family: High Output Current Amplifier (>=50mA), Low Input Bias Current Amp (<=10pA), Low Noise Amp (<=10nV/rtHz), Low Offset Voltage Amplifier (<=500uV), Low Supply Voltage Amplifier (<=2.7V), Precision Amplifier; Iq per channel(Max)(mA): 1.6; Eco-Plan: Green (RoHS & no Sb/Br); IIB(Max)(pA): 400; Total Supply Voltage(Max)(+5V is 5, +/-5V is 10): 5.5; Slew Rate(Typ)(V/us): 10; CMRR(Min)(dB): 100; Vn at 1kHz(Typ)(nV/rtHz): 8.5; Number of Channels: 2; Offset Drift(Typ)(uV/C): 1.5; Total Supply Voltage(Min)(+5V is 5, +/-5V is 10): 1.8; AEC Category: Q200; AEC Qualified: N; CompType: IC; SizeAreaWB_mm2: 23.6; SizeArea_mm2: 14.7; SizeX_mm: 4.9; SizeY_mm: 3; SizeZ_mm: 1.1
U8 = CMP-0032596-2: Low Noise, Very Low Drift, Precision Series Voltage Reference, DGK0008A (VSSOP-8); Manufacturer: Texas Instruments; Temp Coeff(Max)(ppm/ degree C): 3; Iout/Iz(Max)(mA): 10; VI(Min)(V): 3.2; Eco-Plan: Green (RoHS & no Sb/Br); Initial Accuracy @ 25/deg C(%): 0.05; Iq(Max)(uA): 1000; VI(Max)(V): 18; Rating: Catalog; AEC Category: Q200; AEC Qualified: N; CompType: IC; SizeAreaWB_mm2: 23.6; SizeArea_mm2: 14.7; SizeX_mm: 4.9; SizeZ_mm: 1.1

## Sheet MCU144E1_Clock_Reset_Boot.SchDoc: Clock, Reset, and Boot
size 431 x 279 mm; DrawnBy: Gustavo Martinez; DocumentNumber: 7; SheetNumber: 4; SheetTotal: 8; PageSetup: Record=PageOptions¦CenterHorizontal=True¦CenterVertical=True¦PrintScale=1.00¦XCorrection=1.00¦YCorrection=1.00¦PrintKind=0¦BorderSize=5000000¦LeftOffset=0¦BottomOffset=0¦Orientation=2¦PaperLength=1000¦PaperWidth=1000¦Scale=100¦PaperSource=15¦PrintQuality=600¦MediaType=1¦DitherType=10¦PaperKind=Letter¦PrintScaleMode=1
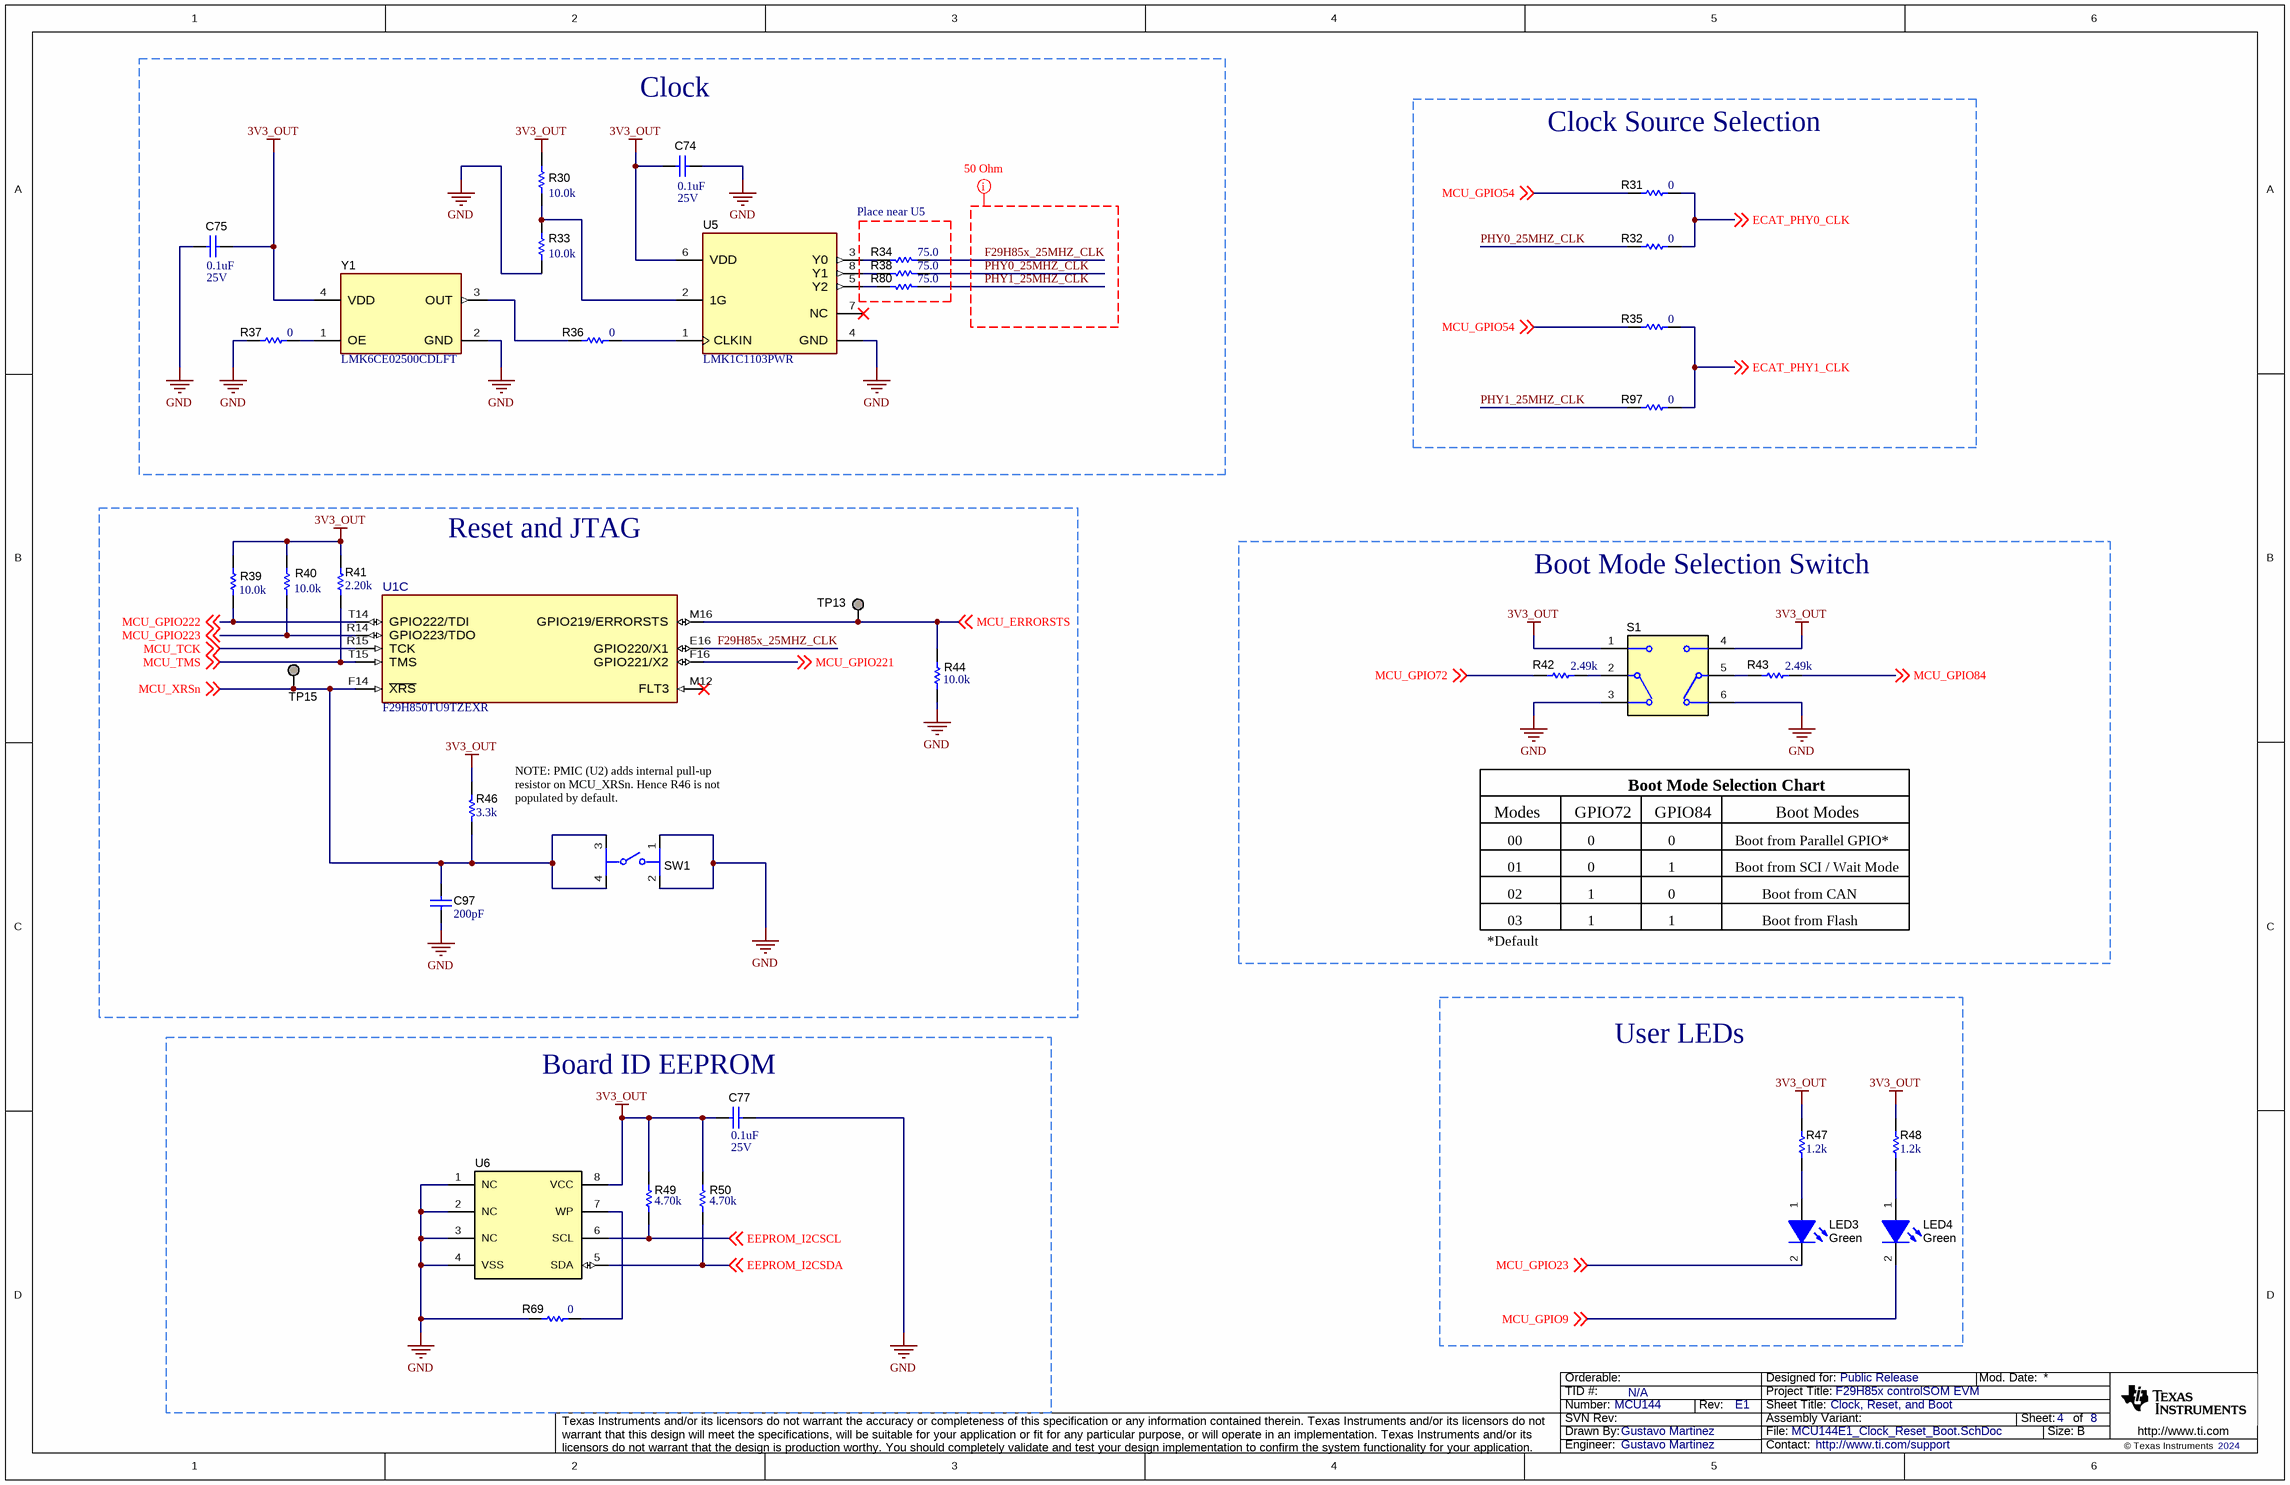
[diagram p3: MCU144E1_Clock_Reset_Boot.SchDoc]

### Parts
C74  VDC_V: 25V  ValueDisplayed: 0.1uF  [0402]  (hidden comment: GRM155R71E104KE14D)
C75  VDC_V: 25V  ValueDisplayed: 0.1uF  [0402]  (hidden comment: GRM155R71E104KE14D)
C77  VDC_V: 25V  ValueDisplayed: 0.1uF  [0402]  (hidden comment: GRM155R71E104KE14D)
C97  ValueDisplayed: 200pF  [0402]  (hidden comment: GRM1555C1H201JA01D)
LED3  value Green  [APHHS1005_Green]  (hidden comment: APHHS1005CGCK)
LED4  value Green  [APHHS1005_Green]  (hidden comment: APHHS1005CGCK)
R30  value 10.0k  [0402]  (hidden comment: AC0402FR-0710KL)
R31  value 0  [0402]  (hidden comment: CRCW04020000Z0ED)
R32  value 0  [0402]  (hidden comment: CRCW04020000Z0ED)
R33  value 10.0k  [0402]  (hidden comment: AC0402FR-0710KL)
R34  ValueDisplayed: 75.0  [0402]  (hidden comment: CRCW040275R0FKED)
R35  value 0  [0402]  (hidden comment: CRCW04020000Z0ED)
R36  ValueDisplayed: 0  [0402]  (hidden comment: CRCW04020000Z0ED)
R37  value 0  [0402]  (hidden comment: CRCW04020000Z0ED)
R38  ValueDisplayed: 75.0  [0402]  (hidden comment: CRCW040275R0FKED)
R39  value 10.0k  [0402]  (hidden comment: AC0402FR-0710KL)
R40  value 10.0k  [0402]  (hidden comment: AC0402FR-0710KL)
R41  ValueDisplayed: 2.20k  [0402]  (hidden comment: CRCW04022K20FKED)
R42  ValueDisplayed: 2.49k  [0402]  (hidden comment: CRCW04022K49FKED)
R43  ValueDisplayed: 2.49k  [0402]  (hidden comment: CRCW04022K49FKED)
R44  value 10.0k  [0402]  (hidden comment: AC0402FR-0710KL)
R46  ValueDisplayed: 3.3k  [0402]  (hidden comment: CRCW04023K30JNED)
R47  ValueDisplayed: 1.2k  [0402]  (hidden comment: CRCW04021K20JNED)
R48  ValueDisplayed: 1.2k  [0402]  (hidden comment: CRCW04021K20JNED)
R49  value 4.70k  [0402]  (hidden comment: CRG0402F4K7)
R50  value 4.70k  [0402]  (hidden comment: CRG0402F4K7)
R69  ValueDisplayed: 0  [0402]  (hidden comment: CRCW04020000Z0ED)
R80  ValueDisplayed: 75.0  [0402]  (hidden comment: CRCW040275R0FKED)
R97  value 0  [0402]  (hidden comment: CRCW04020000Z0ED)
S1  CAS-D20TA  [SW_CAS-D20TA]  (value not drawn)
SW1  PTS810 SJG 250 SMTR LFS  [FP-PTS810 SJG 250 SMTR LFS_SW_SMT_4MM2_3MM2-MFG]  (value not drawn)
TP13  TP_SM_1MM  [TP_SM_1MM]  (value not drawn)  (no BOM)
TP15  CMP-0078143-4  [TESTPOINT]  (value not drawn)  (no BOM)
U1  F29H850TU9TZEXR  [ZEX0256A-MFG]  (part C of 4)
U5  LMK1C1103PWR  [PW0008A-MFG]
U6  CAT24C16WI-GT3  [SOIC-8]  (value not drawn)
Y1  LMK6CE02500CDLFT  [DLF0004A-MFG]

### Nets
3V3_OUT: C74.1 C75.1 C77.1 R30.2 R39.2 R40.2 R41.2 R46.2 R47.2 R48.2 R49.2 R50.2 S1.1 S1.4 U5.6(VDD) U6.8(VCC) Y1.4(VDD)
GND: C74.2 C75.2 C77.2 C97.2 R33.1 R37.1 R44.1 R69.2 S1.3 S1.6 SW1.1 SW1.2 U5.4(GND) U6.1(NC) U6.2(NC) U6.3(NC) U6.4(VSS) Y1.2(GND)
ECAT_PHY0_CLK: R31.1 R32.1 ; off-sheet ECAT_PHY0_CLK
ECAT_PHY1_CLK: R35.1 R97.1 ; off-sheet ECAT_PHY1_CLK
EEPROM_I2CSCL: R49.1 U6.6(SCL) ; off-sheet EEPROM_I2CSCL
EEPROM_I2CSDA: R50.1 U6.5(SDA) ; off-sheet EEPROM_I2CSDA
F29H85x_25MHZ_CLK: R34.2 U1.E16(GPIO220/X1)
MCU_ERRORSTS: R44.2 TP13.1 U1.M16(GPIO219/ERRORSTS) ; off-sheet MCU_ERRORSTS
MCU_GPIO9: LED4.2(K) ; off-sheet MCU_GPIO9
MCU_GPIO23: LED3.2(K) ; off-sheet MCU_GPIO23
MCU_GPIO54: R31.2 R35.2 ; off-sheet MCU_GPIO54
MCU_GPIO72: R42.2 ; off-sheet MCU_GPIO72
MCU_GPIO84: R43.1 ; off-sheet MCU_GPIO84
MCU_GPIO221: U1.F16(GPIO221/X2) ; off-sheet MCU_GPIO221
MCU_GPIO222: R39.1 U1.T14(GPIO222/TDI) ; off-sheet MCU_GPIO222
MCU_GPIO223: R40.1 U1.R14(GPIO223/TDO) ; off-sheet MCU_GPIO223
MCU_TCK: U1.R15(TCK) ; off-sheet MCU_TCK
MCU_TMS: R41.1 U1.T15(TMS) ; off-sheet MCU_TMS
MCU_XRSn: C97.1 R46.1 SW1.3 SW1.4 TP15.1 U1.F14(~{XRS}) ; off-sheet MCU_XRSn
PHY0_25MHZ_CLK: R32.2 R38.2
PHY1_25MHZ_CLK: R80.2 R97.2
NetLED3_1: LED3.1(A) R47.1
NetLED4_1: LED4.1(A) R48.1
NetR30_1: R30.1 R33.2 U5.2(1G)
NetR34_1: R34.1 U5.3(Y0)
NetR36_1: R36.1 Y1.3(OUT)
NetR36_2: R36.2 U5.1(CLKIN)
NetR37_2: R37.2 Y1.1(OE)
NetR38_1: R38.1 U5.8(Y1)
NetR42_1: R42.1 S1.2(C)
NetR43_2: R43.2 S1.5(C)
NetR69_1: R69.1 U6.7(WP)
NetR80_1: R80.1 U5.5(Y2)

Not connected (* = marked no-connect by the designer): U1 M12(FLT3)*; U5 7(NC)*

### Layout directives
mark named 50 Ohm: 3V3_OUT, F29H85x_25MHZ_CLK, GND, PHY0_25MHZ_CLK, PHY1_25MHZ_CLK

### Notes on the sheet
- Clock
- Clock Source Selection
- Place near U5
- Reset and JTAG
- Boot Mode Selection Switch
- NOTE: PMIC (U2) adds internal pull-up resistor on MCU_XRSn. Hence R46 is not populated by default.
- Modes
- GPIO72
- Boot Mode Selection Chart
- GPIO84
- Boot Modes
- 00
- 01
- 02
- 0
- 1
- Boot from Parallel GPIO*
- Boot from SCI / Wait Mode
- Boot from CAN
- *Default
- 03
- Boot from Flash
- (near C77) Board ID EEPROM
- User LEDs

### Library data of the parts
C74 C75 C77 = CMP-0006659-2: as C85 on sheet MCU144E1_ADC
C97 = CMP-0006437-2: CAP, CERM, 200 pF, 50 V, +/- 5%, C0G/NP0, 0402; Manufacturer: MuRata; TaMin_C: -55°C; Polarized: N; SizeAreaWB_mm2: 3; Value1: Unknown; U/M: EA; Value: 200pF; TaMax_C: 125°C; SizeZ_mm: 0.6; SizeX_mm: 1; SizeY_mm: 0.5; Value2: 50V; AEC Category: Q200
LED3 LED4 = CMP-0067682-2: LED, Green, SMD; Manufacturer: Kingbright; Value1: 0.075W; Vf_V: 2.1V; Vr_V: 5V; SizeArea_mm2: 0.5; Power_TotalModule: 75mW; Tjmax_C: 85°C; Angle: 120.0; SizeAreaWB_mm2: 3.0; SizeX_mm: 1.0; Ir_A: 10µA; Io_A: 20mA; SizeZ_mm: 0.6
R30 R33 R39 R40 R44 = CMP-0077731-1: as R3 on sheet MCU144E1_GPIO_Power
R31 R32 R35 R37 R97 = CMP-0026822-3: RES, 0, 5%, 0.063 W, AEC-Q200 Grade 0, 0402; Manufacturer: Vishay-Dale; Power_W: 63mW; TempCo: 200 ppm/C; Value_Code: 0000; EIA_Code: E24; SizeX_mm: 1; SizeY_mm: 0.5; SizeZ_mm: 0.6; Value2: 0.063W; AEC Qualified: Y; VDC_V: 50V; AEC Category: Q200
R34 R38 R80 = CMP-0026544-2: RES, 75.0, 1%, 0.063 W, AEC-Q200 Grade 0, 0402; Manufacturer: Vishay-Dale; Power_W: 63mW; TempCo: 100 ppm/C; Value_Code: 75R0; Value: 75.0; EIA_Code: E96; Res_ohm: 75; SizeX_mm: 1; SizeY_mm: 0.5; SizeZ_mm: 0.6; Value2: 0.063W; AEC Qualified: Y; VDC_V: 50V; AEC Category: Q200; AEC Grade: 0
R36 R69 = CMP-0026822-3: RES, 0, 5%, 0.063 W, AEC-Q200 Grade 0, 0402; Manufacturer: Vishay-Dale; Power_W: 63mW; TempCo: 200 ppm/C; Value_Code: 0000; Value: 0; EIA_Code: E24; SizeX_mm: 1; SizeY_mm: 0.5; SizeZ_mm: 0.6; Value2: 0.063W; AEC Qualified: Y; VDC_V: 50V; AEC Category: Q200
R41 = CMP-0026231-2: RES, 2.20 k, 1%, 0.063 W, AEC-Q200 Grade 0, 0402; Manufacturer: Vishay-Dale; Power_W: 63mW; TempCo: 100 ppm/C; Value_Code: 2k20; Value: 2.20k; Res_ohm: 2.2k; SizeX_mm: 1; SizeY_mm: 0.5; SizeZ_mm: 0.6; Value2: 0.063W; AEC Qualified: Y; AEC Category: Q200; AEC Grade: 0
R42 R43 = CMP-0026237-2: RES, 2.49 k, 1%, 0.063 W, AEC-Q200 Grade 0, 0402; Manufacturer: Vishay-Dale; Power_W: 63mW; TempCo: 100 ppm/C; Value_Code: 2k49; Value: 2.49k; EIA_Code: E96; SizeX_mm: 1; SizeY_mm: 0.5; SizeZ_mm: 0.6; Value2: 0.063W; AEC Qualified: Y; VDC_V: 50V; AEC Category: Q200; AEC Grade: 0
R46 = CMP-0026918-5: RES, 3.3 k, 5%, 0.063 W, AEC-Q200 Grade 0, 0402; Manufacturer: Vishay-Dale; Power_W: 63mW; TempCo: 200 ppm/C; Value_Code: 3k30; Value: 3.3k; EIA_Code: E24; SizeX_mm: 1; SizeY_mm: 0.5; SizeZ_mm: 0.6; Value2: 0.063W; AEC Qualified: Y; VDC_V: 50V; AEC Category: Q200; AEC Grade: 0
R47 R48 = CMP-0026854-5: RES, 1.2 k, 5%, 0.063 W, AEC-Q200 Grade 0, 0402; Manufacturer: Vishay-Dale; Power_W: 63mW; TempCo: 200 ppm/C; Value_Code: 1k20; Value: 1.2k; EIA_Code: E24; SizeX_mm: 1; SizeY_mm: 0.5; SizeZ_mm: 0.6; Value2: 0.063W; AEC Qualified: Y; VDC_V: 50V; AEC Category: Q200; AEC Grade: 0
R49 R50 = CMP-0026631-1: RES, 4.70 k, 1%, 0.063 W, 0402; Manufacturer: TE Connectivity; Power_W: 63mW; TempCo: 100 ppm/C; Value_Code: 4k70; U/M: EA; Res_ohm: 4.7k; SizeX_mm: 1; SizeY_mm: 0.5; SizeZ_mm: 0.6; Value2: 0.063W; AEC Qualified: N; AEC Category: Q200
S1 = CMP-0002233-1: as S3 on sheet MCU144E1_ADC
SW1 = CMP-0087265-1: SWITCH TACTILE SPST-NO 0.05A 16V; Manufacturer: C&K Components; CurrentRating_mA: 50mA; SizeZ_mm: 2.7mm
TP13 = CMP-0003825-1: 1mm Test Point, SMT; Manufacturer: Any
TP15 = CMP-0078143-4: TEST POINT.  No entry in BOM.
U1 = CMP-0121934-2: as U1 on sheet MCU144E1_GPIO_Power
U5 = CMP-0094559-1: Clock Clock Buffer IC 1:3 250 MHz 8-TSSOP; Manufacturer: Texas Instruments; TaMax_C: +125°C; Propagation Delay: 1.5ns; SizeZ_mm: 1.2mm; TJmax_C: +150°C; Number Of Inputs: 1; Max Supply Voltage: 3.465V; Min Supply Voltage: 1.71V; Standoff Height: 0.05mm; Number Of Outputs: 3; AEC Qualified: No; TaMin_C: -40°C; Logic Function: Non-Inverting; Nominal Supply Current: 8-33mA
U6 = CMP-0082059-1: 16 Kb I2C EEPROM Serial, SOIC-8; Manufacturer: ON Semiconductor; SizeArea_mm2: 29.351; SizeAreaWB_mm2: 55.131; SizeY_mm: 4.9; SizeZ_mm: 1.75; SizeX_mm: 5.99
Y1 = CMP-0096024-2: High-Performance BAW Oscillator; Manufacturer: Texas Instruments; Load Capacitance: 30pF; TJmax_C: +125°C; Frequency Stability: 25ppm; SizeZ_mm: 1mm; Max Supply Current: 50mA; Min Supply Voltage: 2.375V; Standoff Height: 0mm; Frequency_Fixed: 25MHz; Max Supply Voltage: 3.465V; TaMax_C: +105°C; AEC Qualified: No; TaMin_C: -40°C; AEC Category: Q200; CompType: IC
